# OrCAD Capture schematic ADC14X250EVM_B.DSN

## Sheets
1 PAGE1 BLOCK DIAGRAM: title: BLOCK DIAGRAM; rev: B; note: ADC14X250 EVM
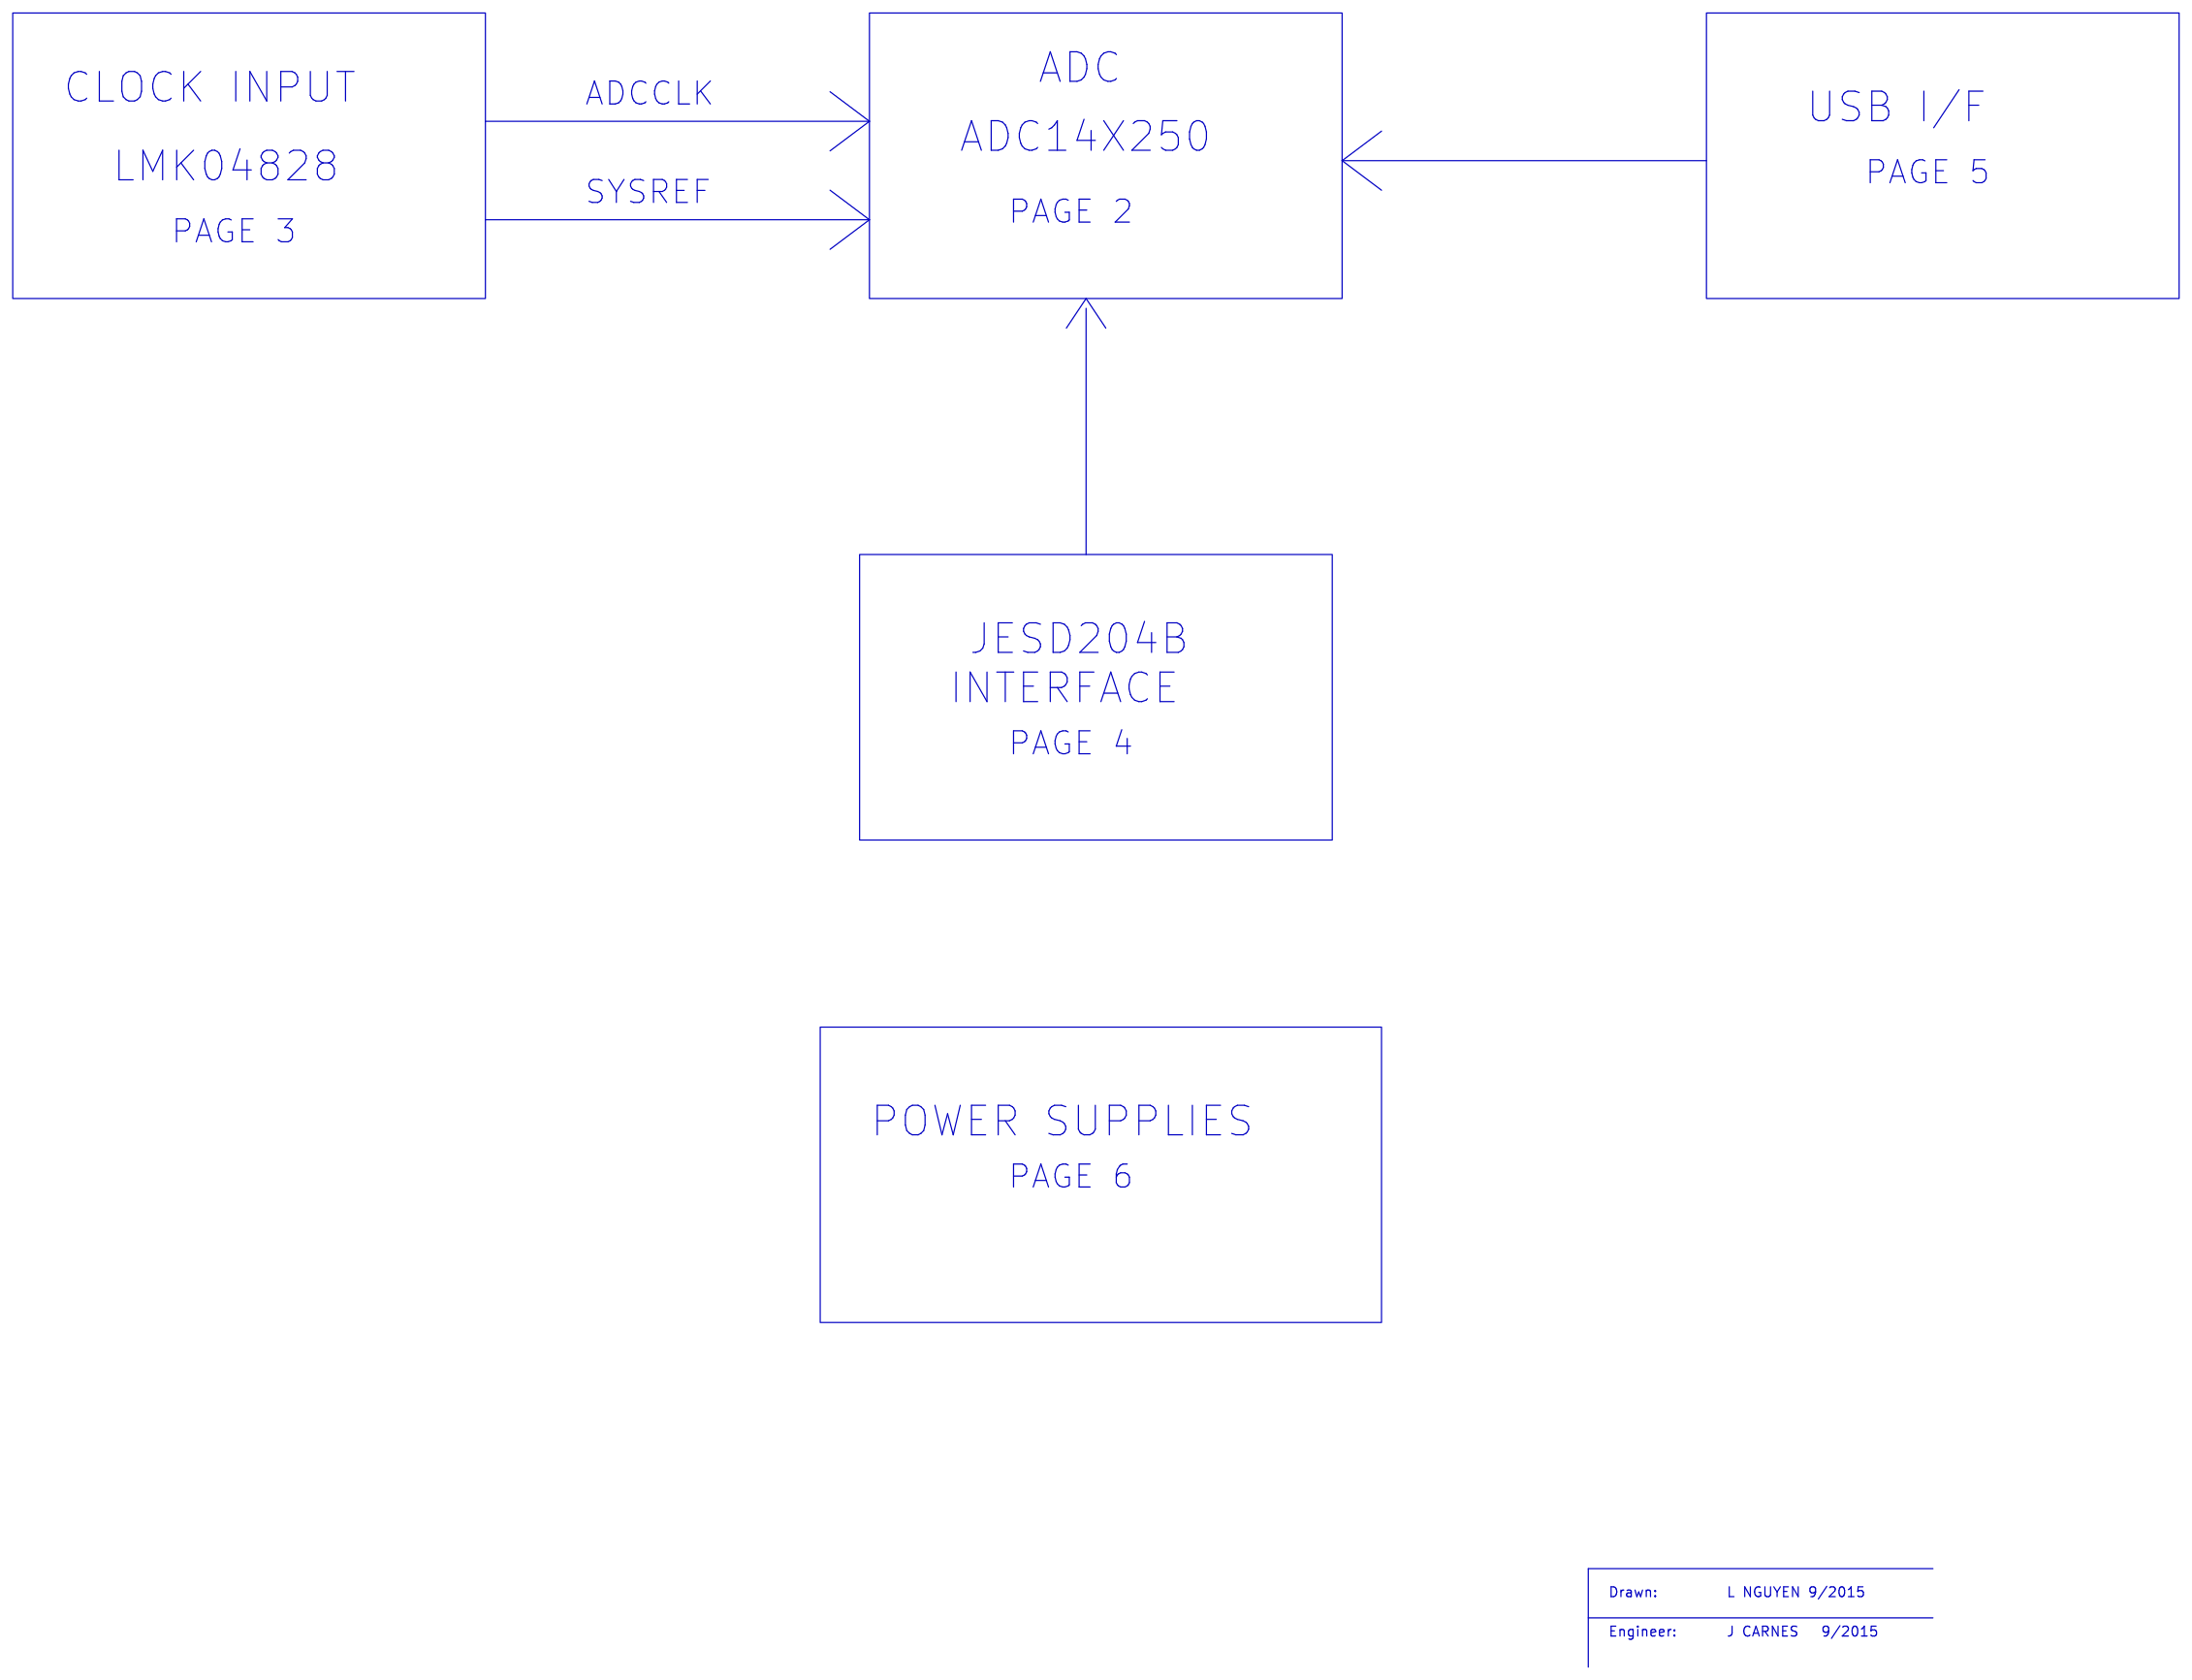
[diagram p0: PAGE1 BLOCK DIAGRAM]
2 PAGE2 ADC: size B; title: ADC14X250
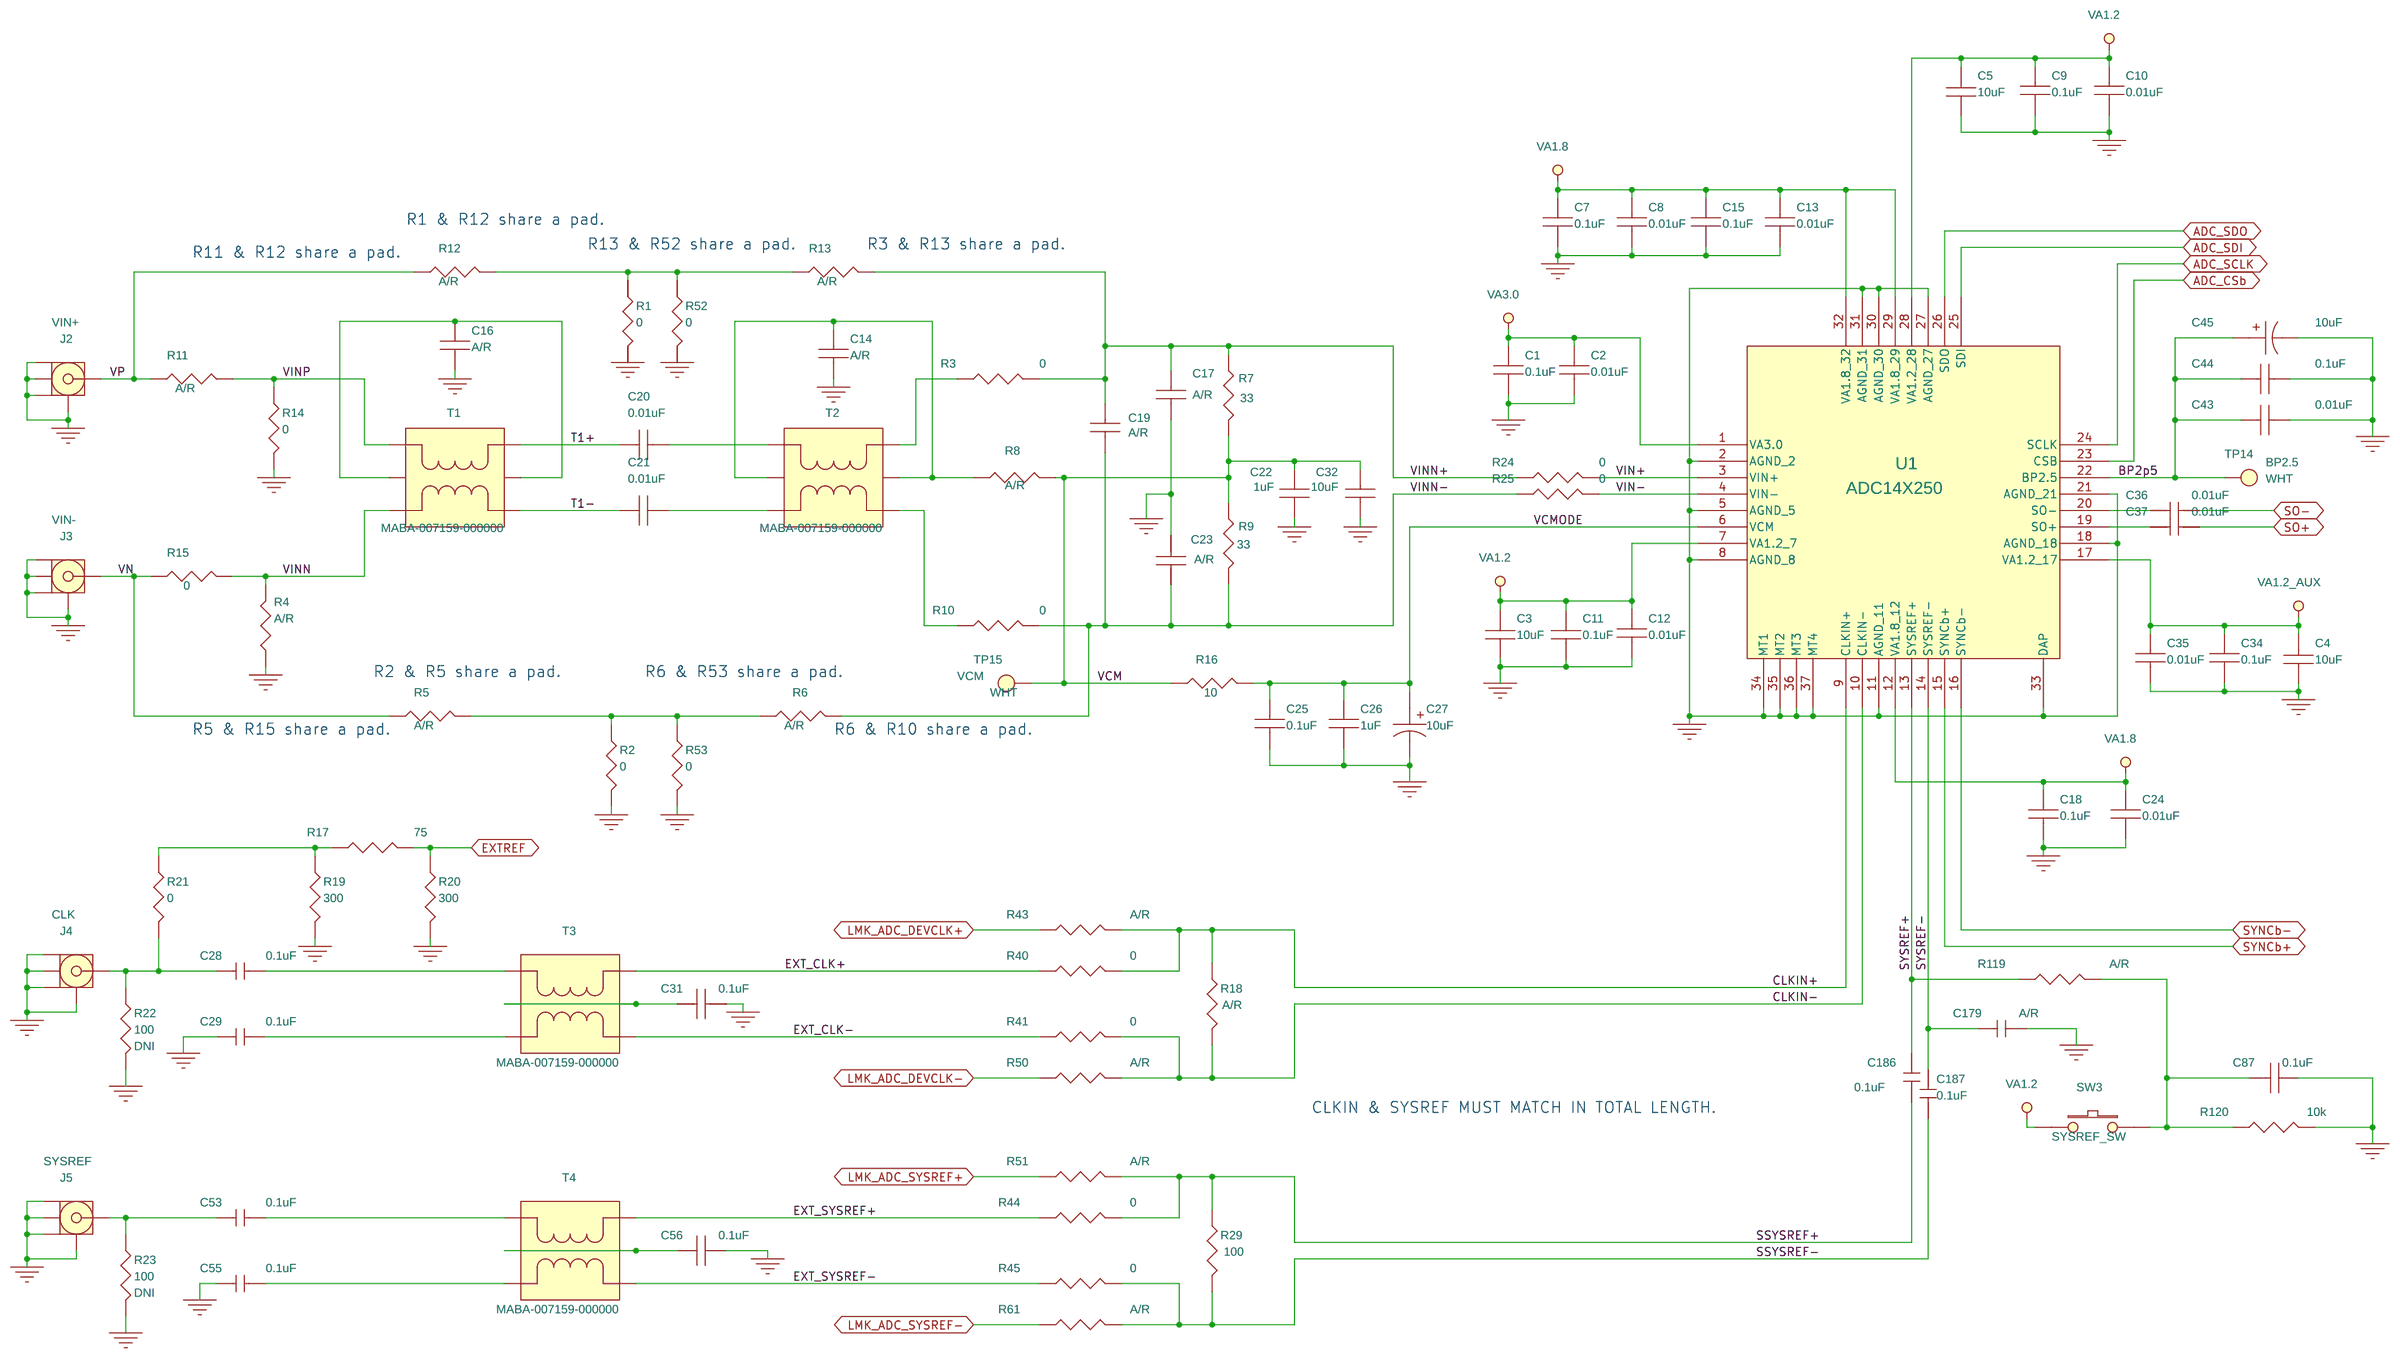
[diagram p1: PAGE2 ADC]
3 PAGE3 LMK: size B; title: LMK04828
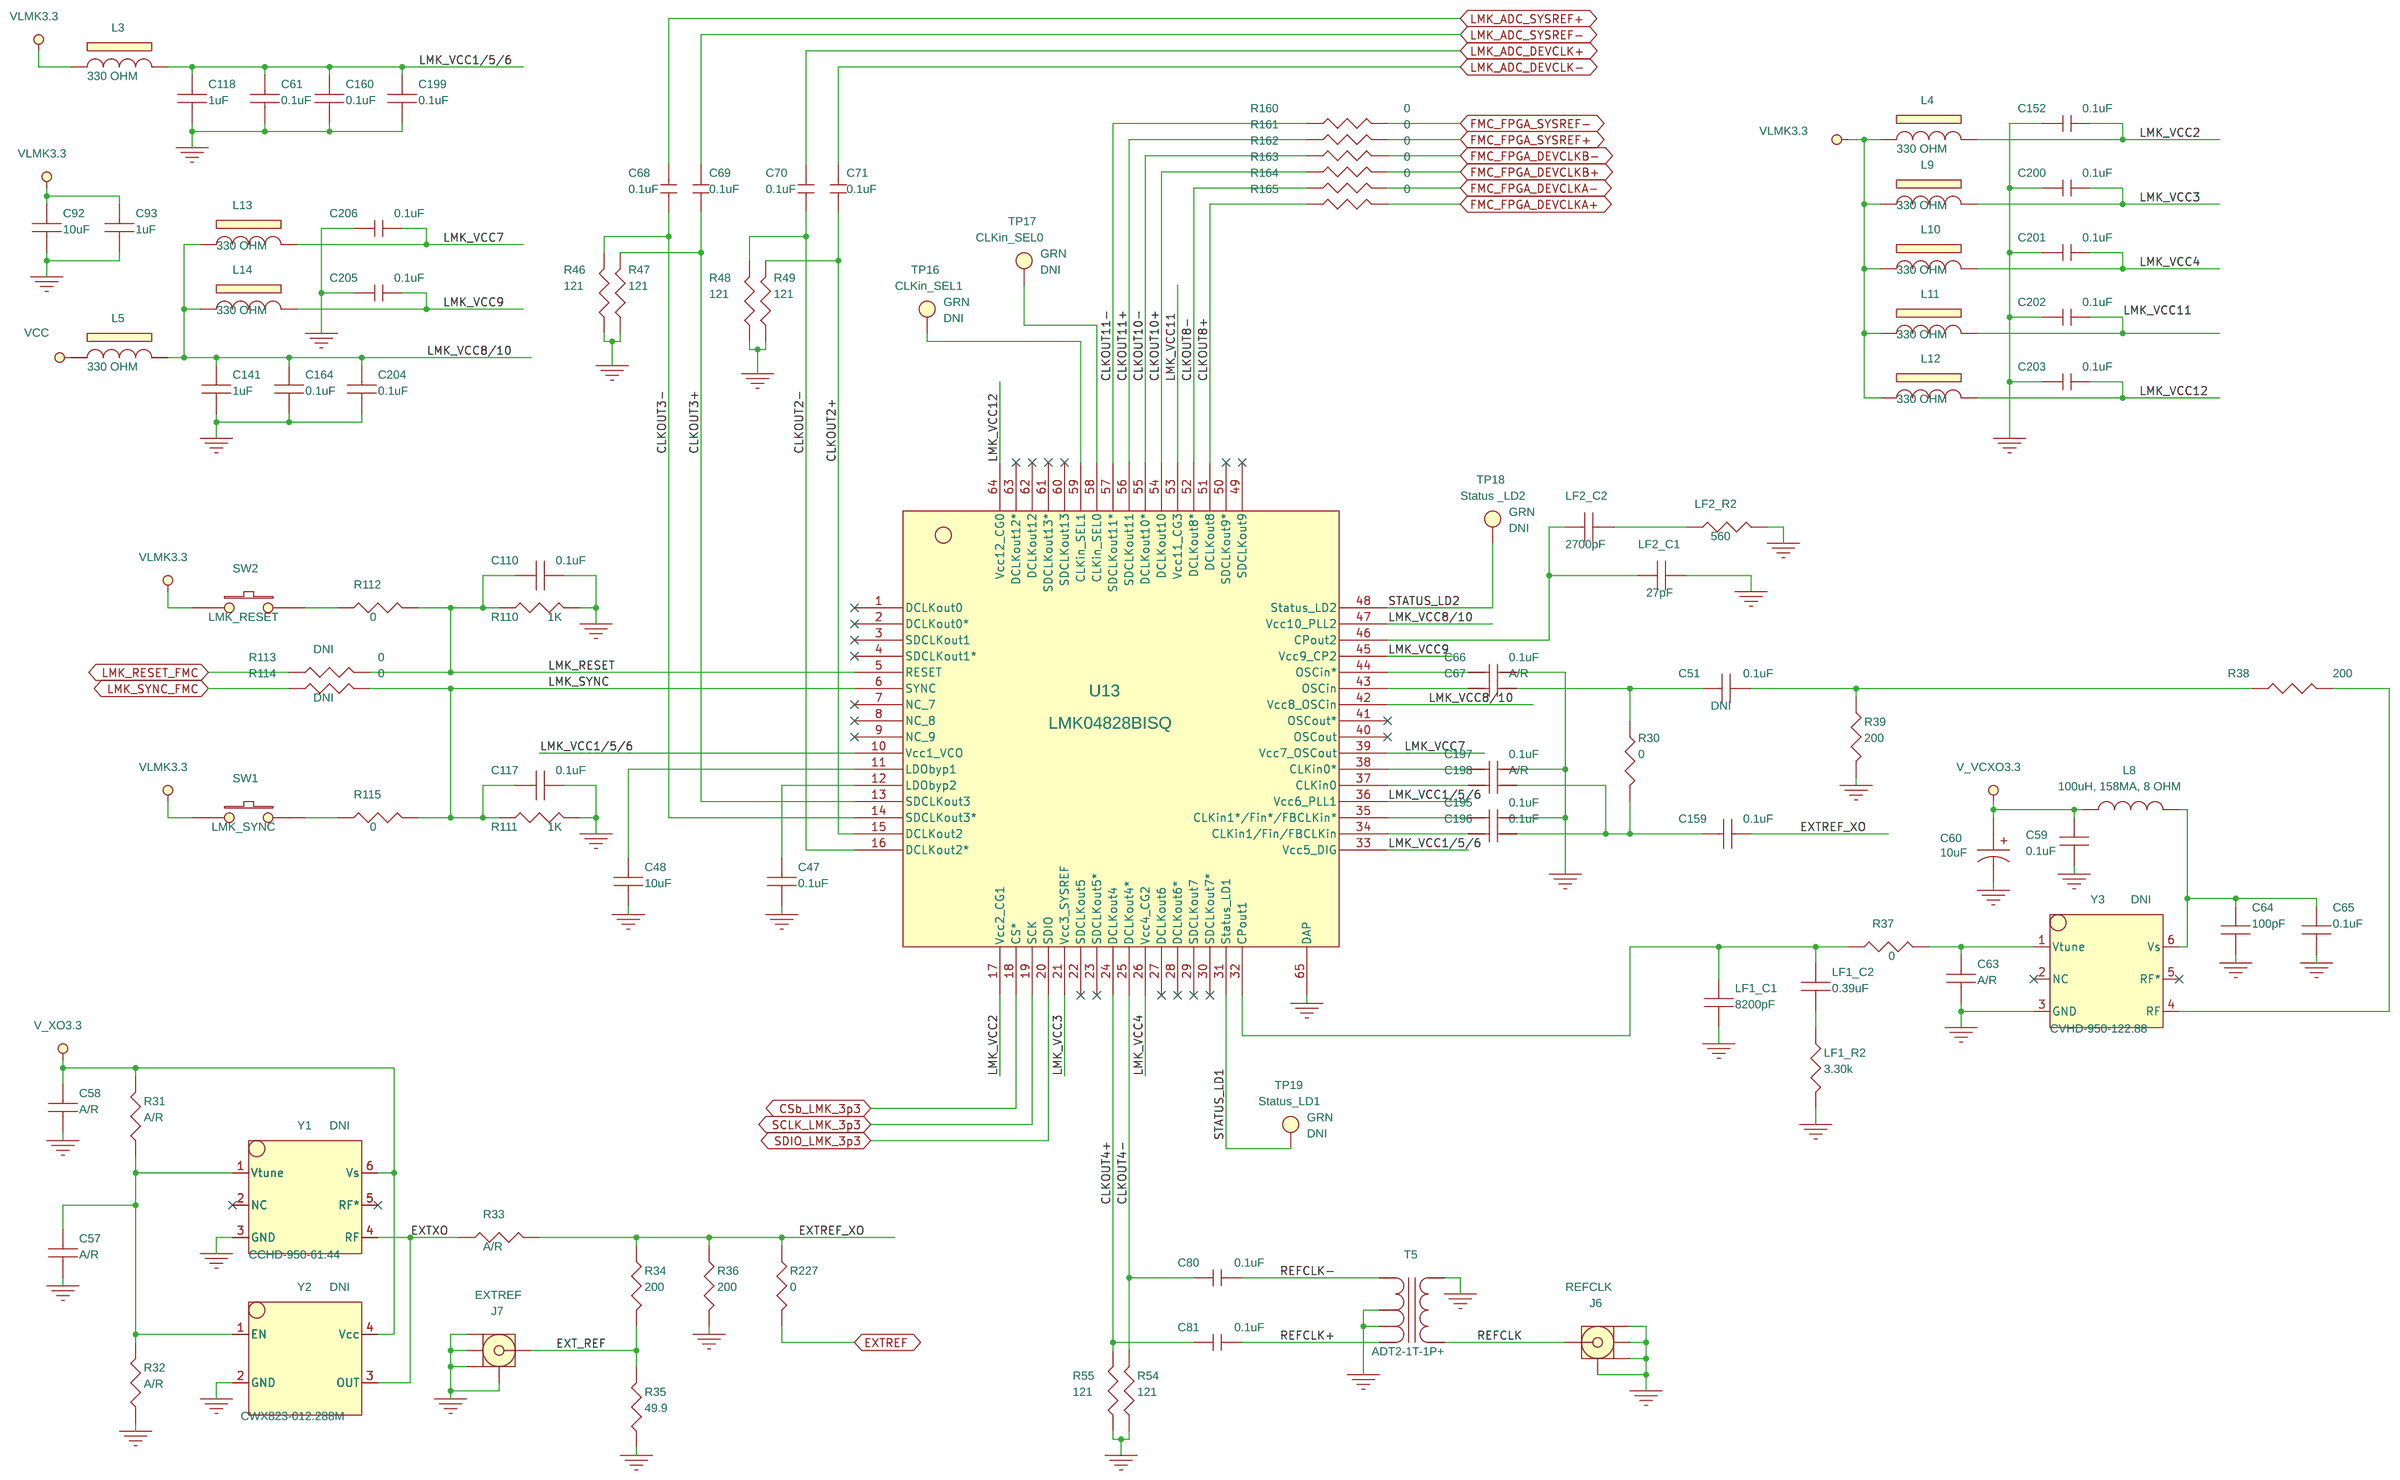
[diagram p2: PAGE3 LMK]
4 PAGE4 FMC: size B; title: FMC
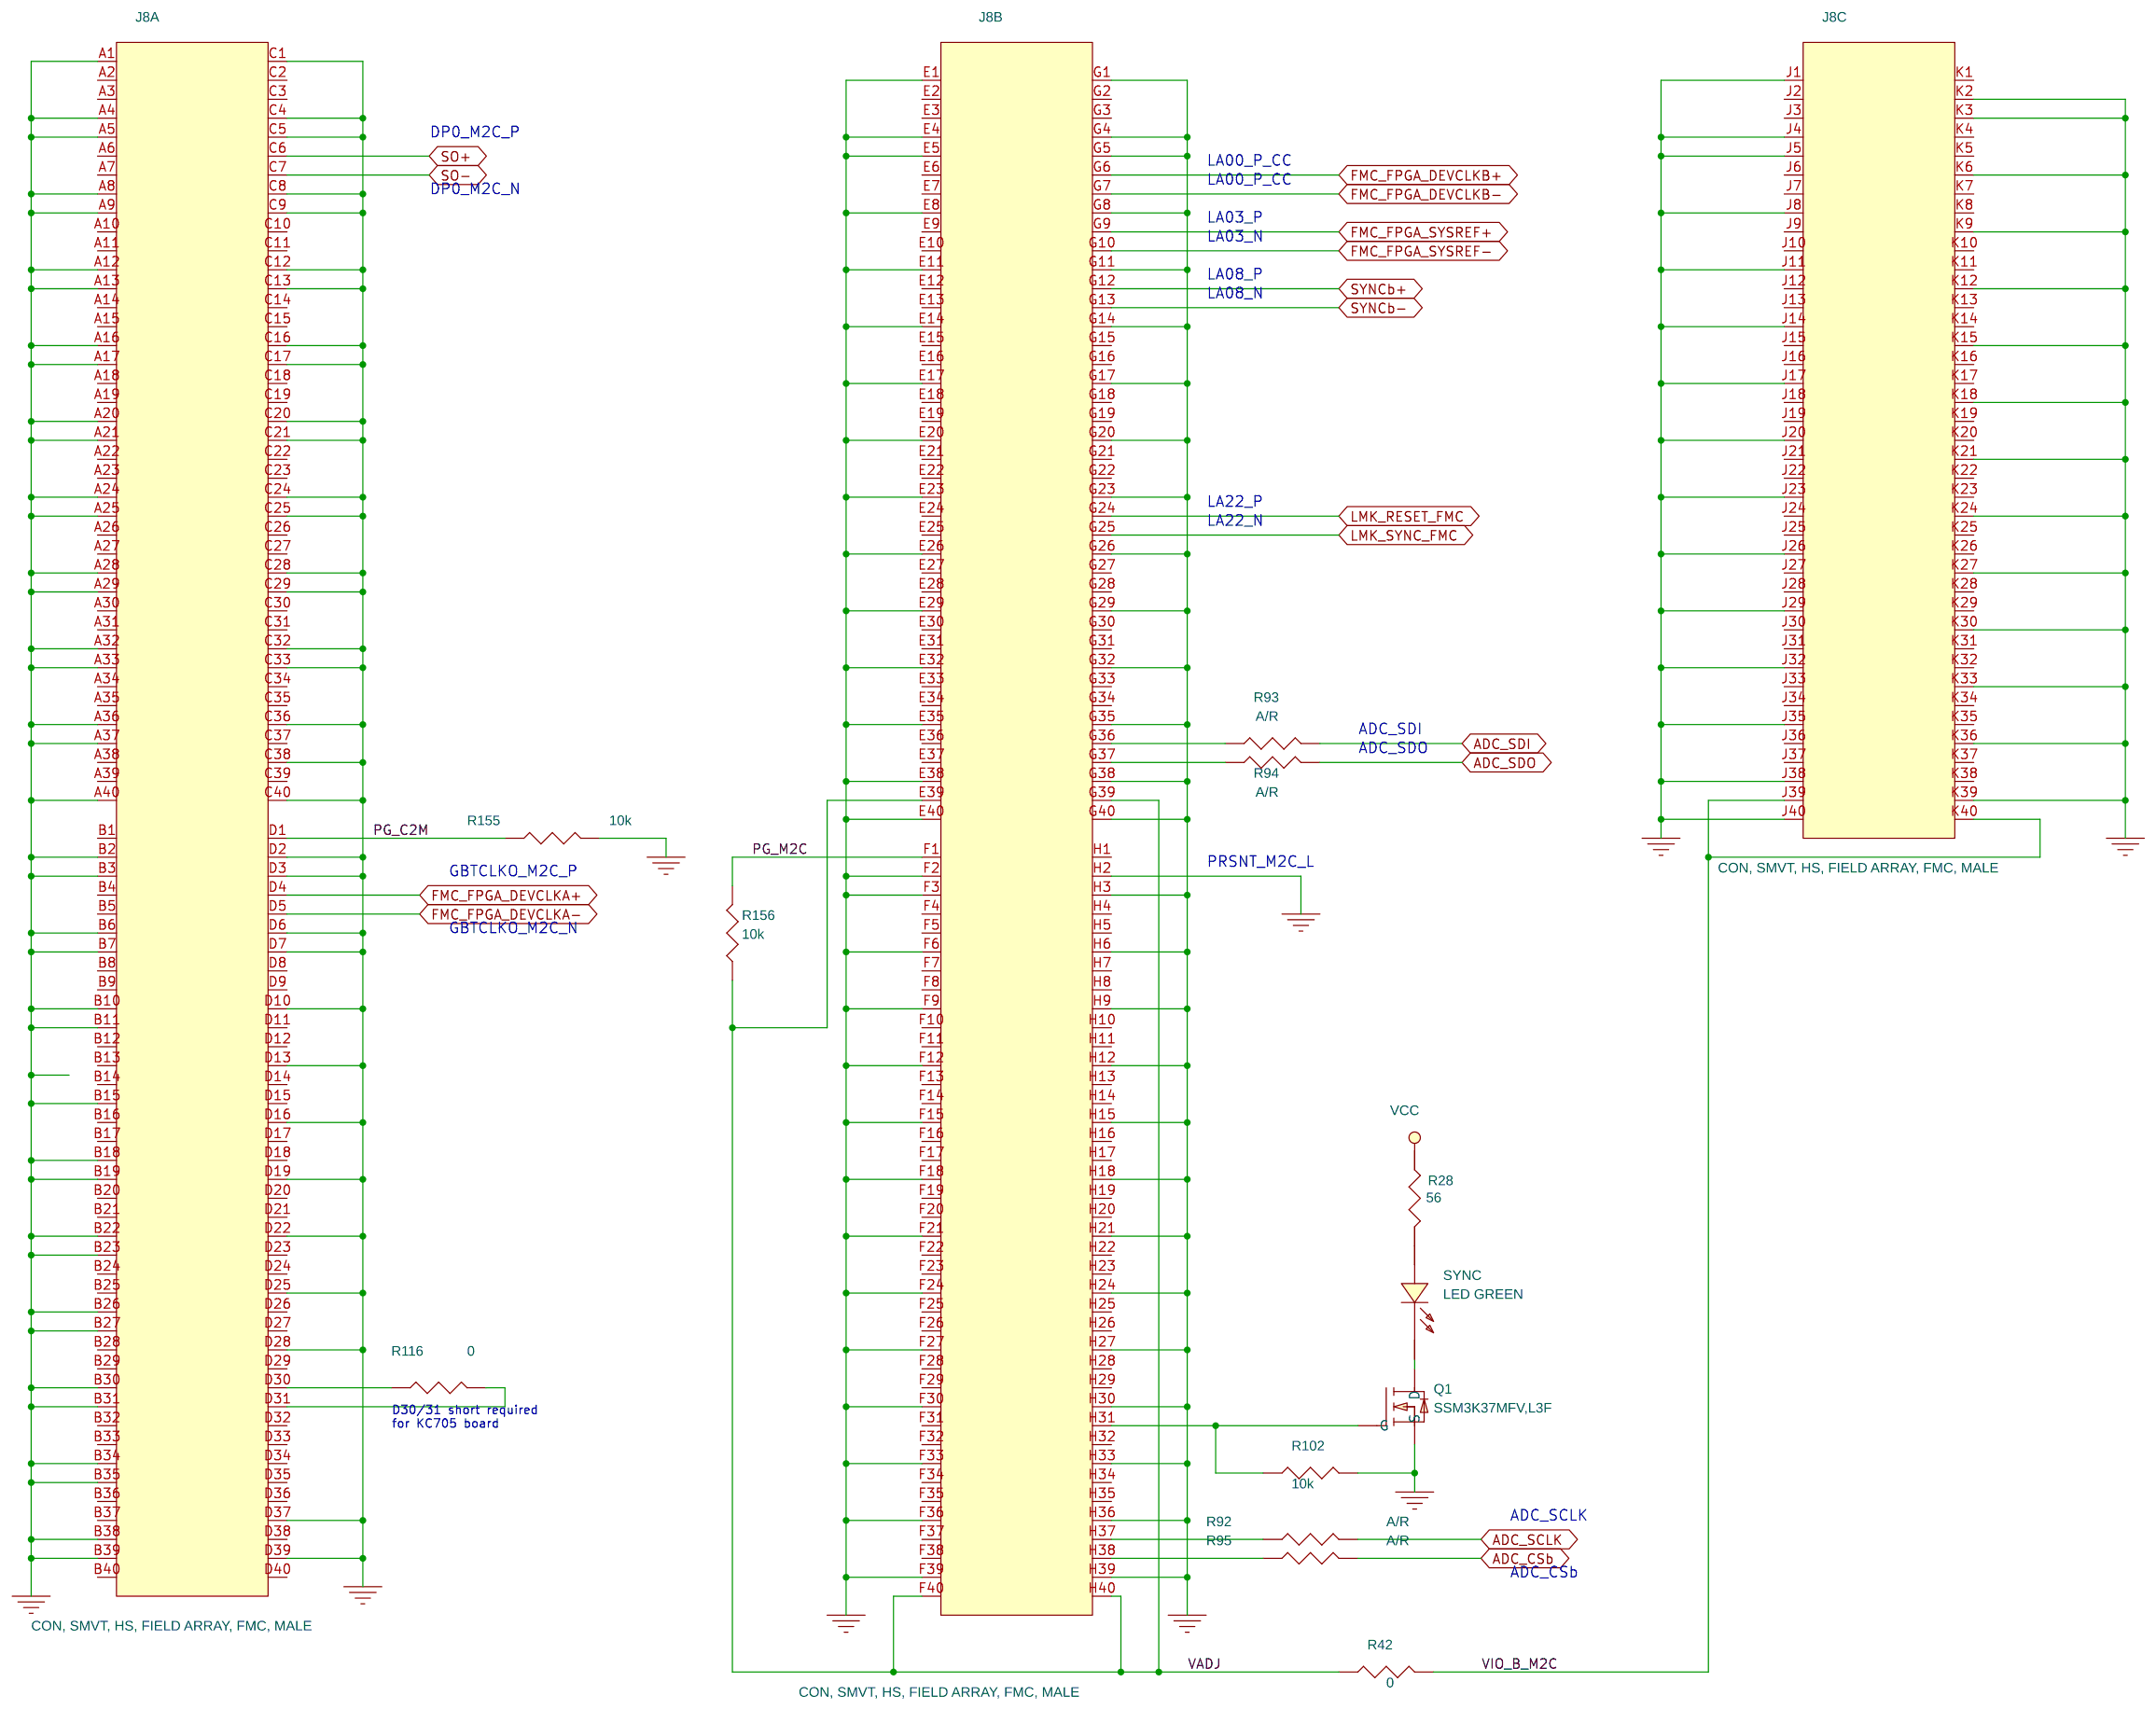
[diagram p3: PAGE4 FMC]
5 PAGE5 INTERFACE: size B; title: USB I/F
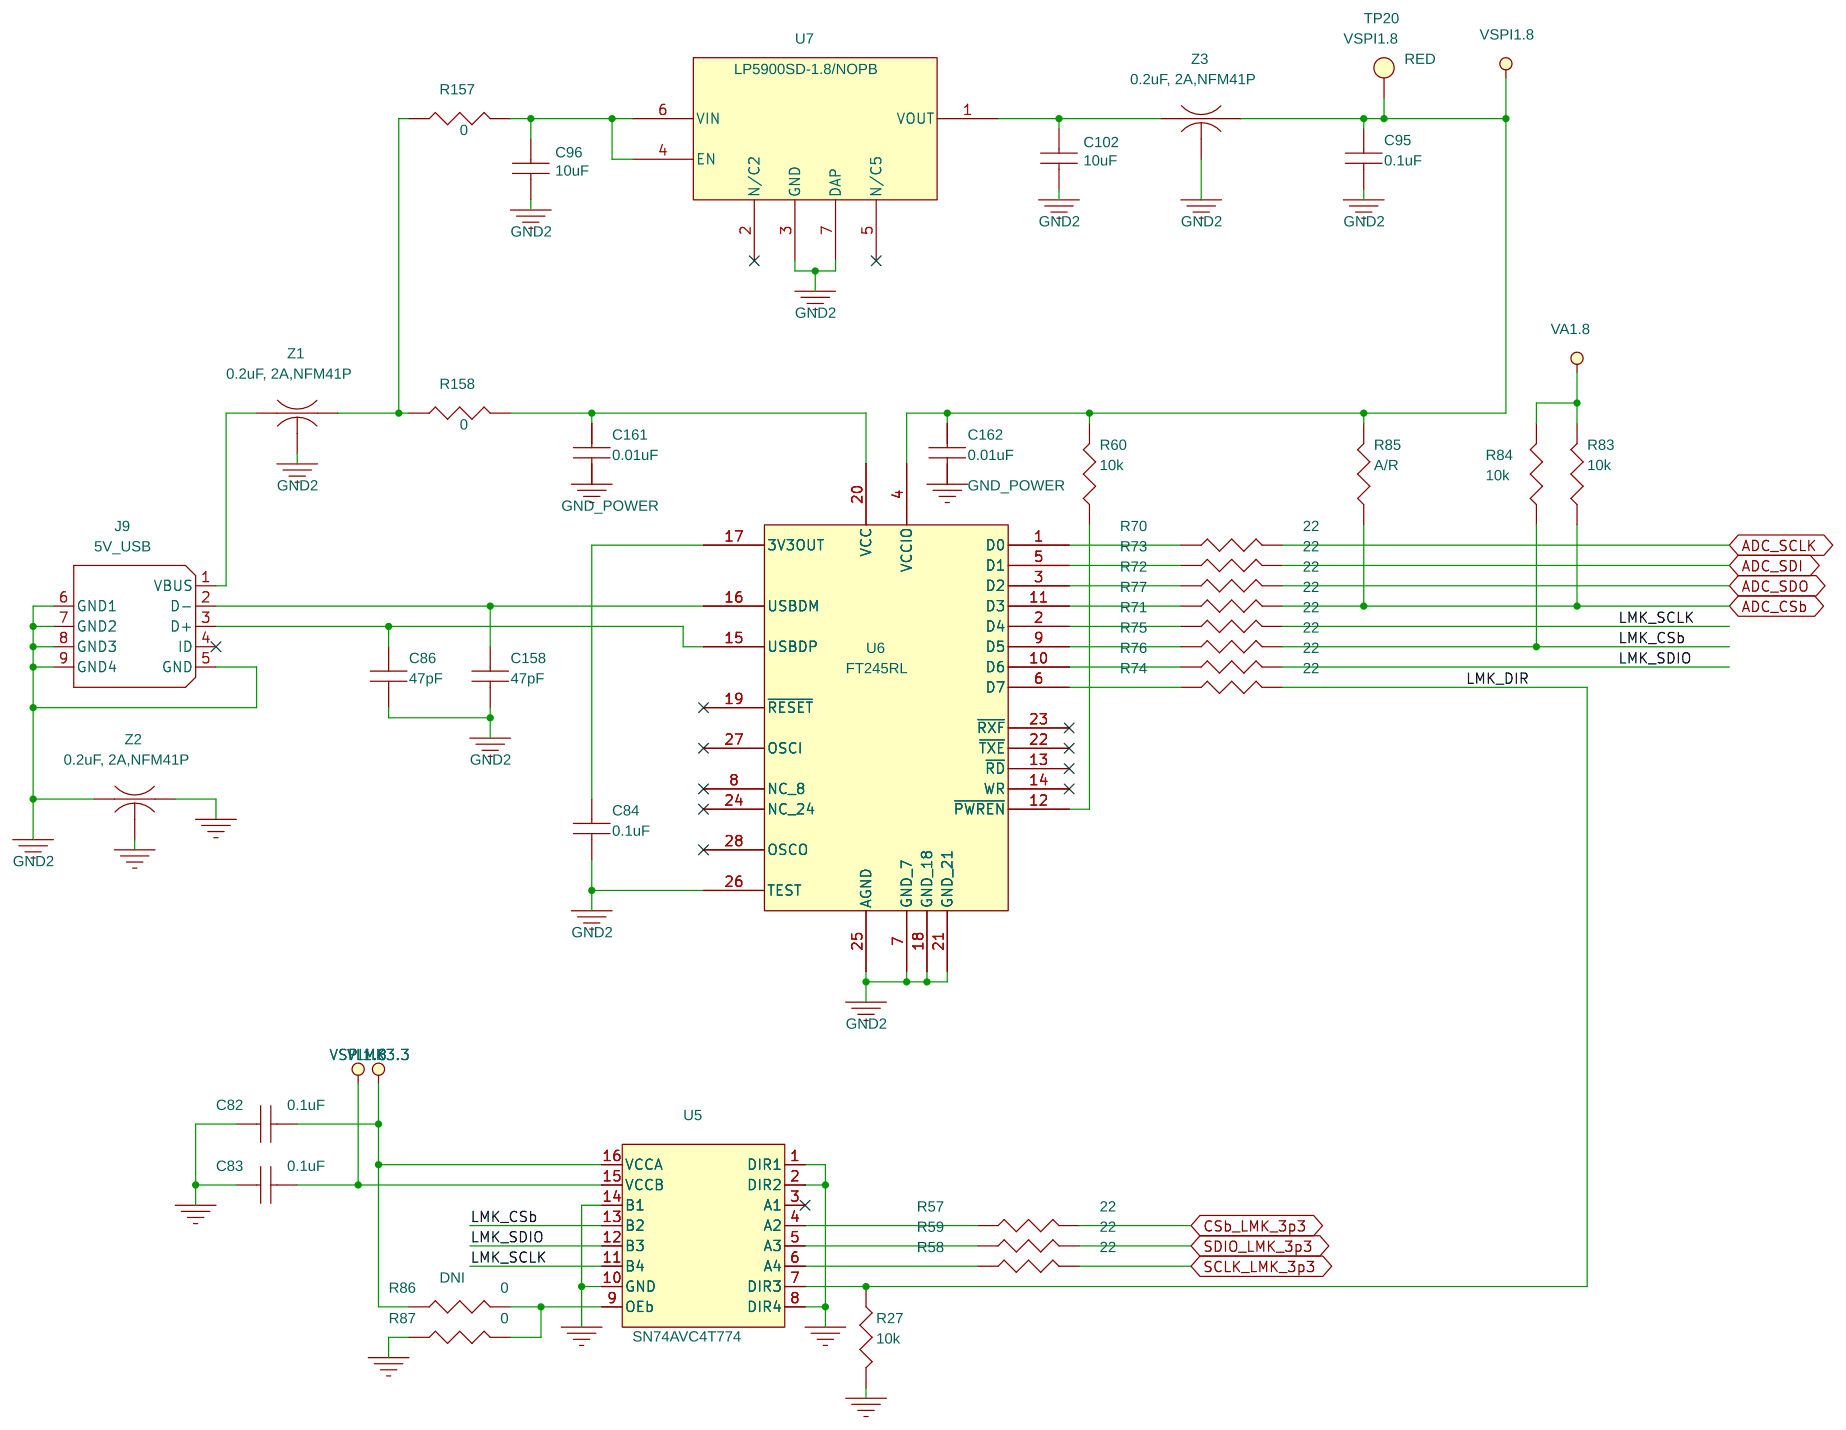
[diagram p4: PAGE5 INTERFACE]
6 PAGE6 POWER: size B; title: POWER
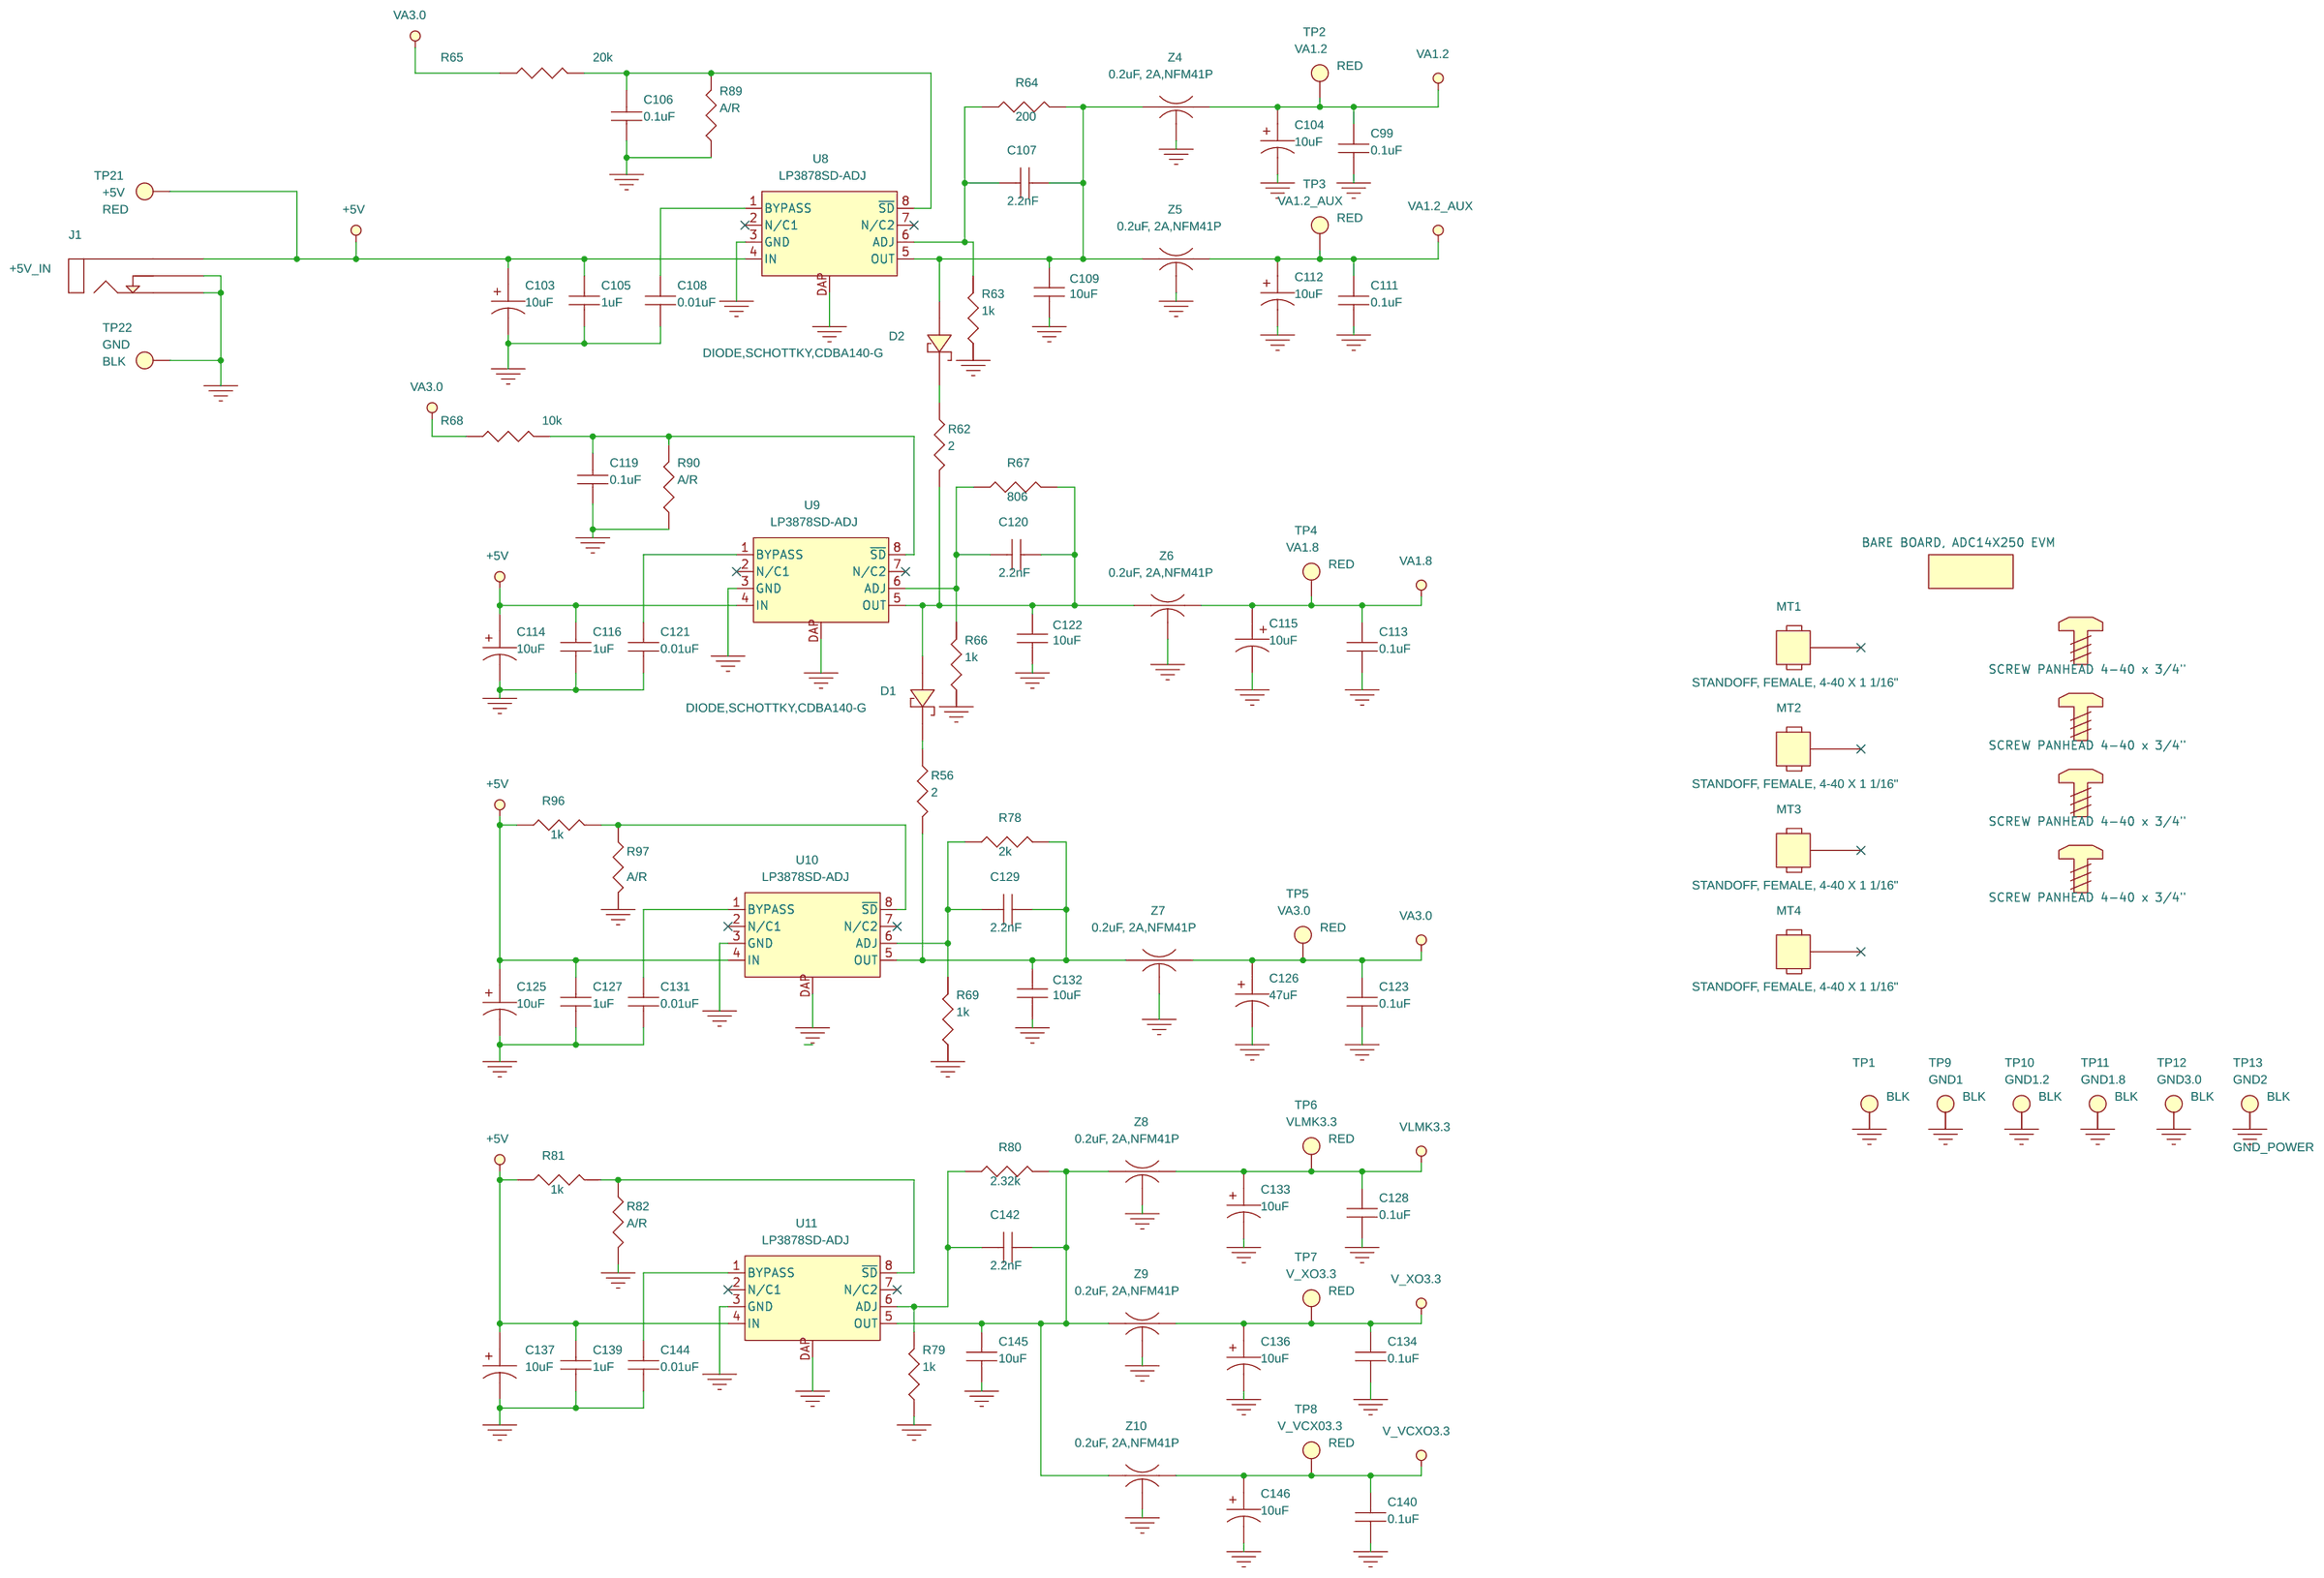
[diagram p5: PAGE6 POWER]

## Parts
sheet PAGE2 ADC
C1  0.1uF  [C0402_NO_SS]
C2  0.01uF  [0201]
C3  10uF  [C0402_NO_SS]
C4  10uF  [C0402_NO_SS]
C5  10uF  [C0402_NO_SS]
C7  0.1uF  [C0402_NO_SS]
C8  0.01uF  [0201]
C9  0.1uF  [C0402_NO_SS]
C10  0.01uF  [0201]
C11  0.1uF  [C0402_NO_SS]
C12  0.01uF  [0201]
C13  0.01uF  [0201]
C14  A/R  [C0402_NO_SS]
C15  0.1uF  [C0402_NO_SS]
C16  A/R  [C0402_NO_SS]
C17  A/R  [0201]
C18  0.1uF  [C0402_NO_SS]
C19  A/R  [C0402_NO_SS]
C20  0.01uF  [C0402_NO_SS]
C21  0.01uF  [C0402_NO_SS]
C22  1uF  [C0402_NO_SS]
C23  A/R  [0201]
C24  0.01uF  [0201]
C25  0.1uF  [0201]
C26  1uF  [0508]
C27  10uF  [cap_a-case]
C28  0.1uF  [0603]
C29  0.1uF  [0603]
C31  0.1uF  [0603]
C32  10uF  [0612]
C34  0.1uF  [C0402_NO_SS]
C35  0.01uF  [0201]
C36  0.01uF  [0201]
C37  0.01uF  [0201]
C43  0.01uF  [0201]
C44  0.1uF  [C0402_NO_SS]
C45  10uF  [cap_a-case]
C53  0.1uF  [0603]
C55  0.1uF  [0603]
C56  0.1uF  [0603]
C87  0.1uF  [smd_size0402]
C179  A/R  [0201]
C186  0.1uF  [0201]
C187  0.1uF  [0201]
J2  CONN, SMA, JACK, 50 OHM, EDGE  [con_sma-edge]
J3  CONN, SMA, JACK, 50 OHM, EDGE  [con_sma-edge]
J4  CONN, SMA, JACK, 50 OHM, EDGE  [con_sma-edge]
J5  CONN, SMA, JACK, 50 OHM, EDGE  [con_sma-edge]
R1  0  [C0402_NO_SS]
R2  0  [C0402_NO_SS]
R3  0  [0201]
R4  A/R  [C0402_NO_SS]
R5  A/R  [C0402_NO_SS]
R6  A/R  [C0402_NO_SS]
R7  33  [C0402_NO_SS]
R8  A/R  [C0402_NO_SS]
R9  33  [C0402_NO_SS]
R10  0  [0201]
R11  A/R  [C0402_NO_SS]
R12  A/R  [C0402_NO_SS]
R13  A/R  [C0402_NO_SS]
R14  0  [C0402_NO_SS]
R15  0  [C0402_NO_SS]
R16  10  [C0402_NO_SS]
R17  75  [0402]
R18  A/R  [0201]
R19  300  [0402]
R20  300  [0402]
R21  0  [C0402_NO_SS]
R22  100  [C0402_NO_SS]
R23  100  [C0402_NO_SS]
R24  0  [0201]
R25  0  [0201]
R29  100  [0201]
R40  0  [C0402_NO_SS]
R41  0  [C0402_NO_SS]
R43  A/R  [C0402_NO_SS]
R44  0  [C0402_NO_SS]
R45  0  [C0402_NO_SS]
R50  A/R  [C0402_NO_SS]
R51  A/R  [C0402_NO_SS]
R52  0  [C0402_NO_SS]
R53  0  [C0402_NO_SS]
R61  A/R  [C0402_NO_SS]
R119  A/R  [0201]
R120  10k  [C0402_NO_SS]
SW3  SW, PUSHBUTTON, SPST-NO  [SW_RESET_PTS635]
T1  MABA-007159-000000  [MABA-007159-000000]
T2  MABA-007159-000000  [MABA-007159-000000]
T3  MABA-007159-000000  [MABA-007159-000000]
T4  MABA-007159-000000  [MABA-007159-000000]
TP14  WHT  [TP_THVT_100_RND]
TP15  WHT  [TP_THVT_100_RND]
U1  ADC14X250  [QFN_32_IRONWOOD_0p5mm]
sheet PAGE3 LMK
C47  0.1uF  [C0402_NO_SS]
C48  10uF  [0805]
C51  0.1uF  [C0402_NO_SS]
C57  A/R  [C0402_NO_SS]
C58  A/R  [C0402_NO_SS]
C59  0.1uF  [0603]
C60  10uF  [smd_size3216]
C61  0.1uF  [C0402_NO_SS]
C63  A/R  [C0402_NO_SS]
C64  100pF  [0603]
C65  0.1uF  [0603]
C66  0.1uF  [0201]
C67  A/R  [0201]
C68  0.1uF  [0201]
C69  0.1uF  [0201]
C70  0.1uF  [0201]
C71  0.1uF  [0201]
C80  0.1uF  [0201]
C81  0.1uF  [0201]
C92  10uF  [0805]
C93  1uF  [C0402_NO_SS]
C110  0.1uF  [smd_size0402]
C117  0.1uF  [smd_size0402]
C118  1uF  [C0402_NO_SS]
C141  1uF  [C0402_NO_SS]
C152  0.1uF  [0201]
C159  0.1uF  [C0402_NO_SS]
C160  0.1uF  [C0402_NO_SS]
C164  0.1uF  [C0402_NO_SS]
C195  0.1uF  [0201]
C196  0.1uF  [0201]
C197  0.1uF  [0201]
C198  A/R  [0201]
C199  0.1uF  [C0402_NO_SS]
C200  0.1uF  [0201]
C201  0.1uF  [0201]
C202  0.1uF  [0201]
C203  0.1uF  [0201]
C204  0.1uF  [C0402_NO_SS]
C205  0.1uF  [0201]
C206  0.1uF  [0201]
J6  CONN, SMA, JACK, 50 OHM, EDGE  [con_sma-edge]
J7  CONN, SMA, JACK, 50 OHM, EDGE  [con_sma-edge]
L3  330 OHM  [r0603]
L4  330 OHM  [r0603]
L5  330 OHM  [r0603]
L8  100uH, 158MA, 8 OHM  [smd_size1812r]
L9  330 OHM  [r0603]
L10  330 OHM  [r0603]
L11  330 OHM  [r0603]
L12  330 OHM  [r0603]
L13  330 OHM  [r0603]
L14  330 OHM  [r0603]
LF1_C1  8200pF  [0603]
LF1_C2  0.39uF  [0603]
LF1_R2  3.30k  [0603]
LF2_C1  27pF  [0603]
LF2_C2  2700pF  [0603]
LF2_R2  560  [0603]
R30  0  [0201]
R31  A/R  [C0402_NO_SS]
R32  A/R  [C0402_NO_SS]
R33  A/R  [C0402_NO_SS]
R34  200  [C0402_NO_SS]
R35  49.9  [C0402_NO_SS]
R36  200  [C0402_NO_SS]
R37  0  [0603]
R38  200  [C0402_NO_SS]
R39  200  [C0402_NO_SS]
R46  121  [C0402_NO_SS]
R47  121  [C0402_NO_SS]
R48  121  [C0402_NO_SS]
R49  121  [C0402_NO_SS]
R54  121  [C0402_NO_SS]
R55  121  [C0402_NO_SS]
R110  1K  [smd_size0402]
R111  1K  [smd_size0402]
R112  0  [C0402_NO_SS]
R113  0  [C0402_NO_SS]
R114  0  [C0402_NO_SS]
R115  0  [C0402_NO_SS]
R160  0  [C0402_NO_SS]
R161  0  [C0402_NO_SS]
R162  0  [C0402_NO_SS]
R163  0  [C0402_NO_SS]
R164  0  [C0402_NO_SS]
R165  0  [C0402_NO_SS]
R227  0  [C0402_NO_SS]
SW1  SW, PUSHBUTTON, SPST-NO  [SW_RESET_PTS635]
SW2  SW, PUSHBUTTON, SPST-NO  [SW_RESET_PTS635]
T5  ADT2-1T-1P+  [ADT1-1WT]
TP16  GRN  [TP_THVT_100_RND]
TP17  GRN  [TP_THVT_100_RND]
TP18  GRN  [TP_THVT_100_RND]
TP19  GRN  [TP_THVT_100_RND]
U13  LMK04828BISQ  [WQFN_64_360x360_0p5mm_PWRPAD]
Y1  CCHD-950-61.44  [soic6_100_wg272_l560]
Y2  CWX823-012.288M  [CWX813]
Y3  CVHD-950-122.88  [soic6_100_wg272_l560]
sheet PAGE4 FMC
J8  CON, SMVT, HS, FIELD ARRAY, FMC, MALE  [CON_SMVT_40x10_SEAM_MTG]  (sections A,B,C)
Q1  SSM3K37MFV,L3F  [sot-723]
R28  56  [smd_size0402]
R42  0  [0603]
R92  A/R  [C0402_NO_SS]
R93  A/R  [C0402_NO_SS]
R94  A/R  [C0402_NO_SS]
R95  A/R  [C0402_NO_SS]
R102  10k  [C0402_NO_SS]
R116  0  [0603]
R155  10k  [0603]
R156  10k  [0603]
SYNC  LED GREEN  [LED_0805]
sheet PAGE5 INTERFACE
C82  0.1uF  [smd_size0402]
C83  0.1uF  [smd_size0402]
C84  0.1uF  [C0402_NO_SS]
C86  47pF  [C0402_NO_SS]
C95  0.1uF  [0603]
C96  10uF  [smd_size1206]
C102  10uF  [smd_size1206]
C158  47pF  [C0402_NO_SS]
C161  0.01uF  [C0402_NO_SS]
C162  0.01uF  [C0402_NO_SS]
J9  CONN, USB, MINI AB, R/A, SMT  [CON_SMRT_USBMNE20_F]
R27  10k  [C0402_NO_SS]
R57  22  [C0402_NO_SS]
R58  22  [C0402_NO_SS]
R59  22  [C0402_NO_SS]
R60  10k  [C0402_NO_SS]
R70  22  [C0402_NO_SS]
R71  22  [C0402_NO_SS]
R72  22  [C0402_NO_SS]
R73  22  [C0402_NO_SS]
R74  22  [C0402_NO_SS]
R75  22  [C0402_NO_SS]
R76  22  [C0402_NO_SS]
R77  22  [C0402_NO_SS]
R83  10k  [C0402_NO_SS]
R84  10k  [C0402_NO_SS]
R85  A/R  [C0402_NO_SS]
R86  0  [smd_size0402]
R87  0  [smd_size0402]
R157  0  [0603]
R158  0  [0603]
TP20  RED  [TP_THVT_100_RND]
U5  SN74AVC4T774  [tssop16_pw]
U6  FT245RL  [FT245RL]
U7  LP5900SD-1.8/NOPB  [sc-mkt-sdb06a_6llp]
Z1  0.2uF, 2A,NFM41P  [nfm41p]
Z2  0.2uF, 2A,NFM41P  [nfm41p]
Z3  0.2uF, 2A,NFM41P  [nfm41p]
sheet PAGE6 POWER
C99  0.1uF  [0603]
C103  10uF  [cap_a-case]
C104  10uF  [cap_a-case]
C105  1uF  [smd_size1206]
C106  0.1uF  [C0402_NO_SS]
C107  2.2nF  [smd_size0603]
C108  0.01uF  [C0402_NO_SS]
C109  10uF  [smd_size1206]
C111  0.1uF  [0603]
C112  10uF  [cap_a-case]
C113  0.1uF  [0603]
C114  10uF  [cap_a-case]
C115  10uF  [cap_a-case]
C116  1uF  [smd_size1206]
C119  0.1uF  [C0402_NO_SS]
C120  2.2nF  [smd_size0603]
C121  0.01uF  [C0402_NO_SS]
C122  10uF  [smd_size1206]
C123  0.1uF  [0603]
C125  10uF  [cap_a-case]
C126  47uF  [cap_a-case]
C127  1uF  [smd_size1206]
C128  0.1uF  [0603]
C129  2.2nF  [smd_size0603]
C131  0.01uF  [C0402_NO_SS]
C132  10uF  [smd_size1206]
C133  10uF  [cap_a-case]
C134  0.1uF  [0603]
C136  10uF  [cap_a-case]
C137  10uF  [cap_a-case]
C139  1uF  [smd_size1206]
C140  0.1uF  [0603]
C142  2.2nF  [smd_size0603]
C144  0.01uF  [C0402_NO_SS]
C145  10uF  [smd_size1206]
C146  10uF  [cap_a-case]
D1  DIODE,SCHOTTKY,CDBA140-G  [ZENER_DO_214AC]
D2  DIODE,SCHOTTKY,CDBA140-G  [ZENER_DO_214AC]
J1  CONN, JACK, PWR  [CON_RAPC722_JACK_THVT_3]
MT1  STANDOFF, FEMALE, 4-40 X 1 1/16"  [MFG125_PLATED]
MT2  STANDOFF, FEMALE, 4-40 X 1 1/16"  [MFG125_PLATED]
MT3  STANDOFF, FEMALE, 4-40 X 1 1/16"  [MFG125_PLATED]
MT4  STANDOFF, FEMALE, 4-40 X 1 1/16"  [MFG125_PLATED]
R56  2  [0603]
R62  2  [0603]
R63  1k  [smd_size0402]
R64  200  [smd_size0402]
R65  20k  [C0402_NO_SS]
R66  1k  [smd_size0402]
R67  806  [smd_size0402]
R68  10k  [smd_size0402]
R69  1k  [smd_size0402]
R78  2k  [smd_size0402]
R79  1k  [smd_size0402]
R80  2.32k  [smd_size0402]
R81  1k  [smd_size0402]
R82  A/R  [smd_size0402]
R89  A/R  [smd_size0402]
R90  A/R  [smd_size0402]
R96  1k  [smd_size0402]
R97  A/R  [smd_size0402]
TP1  BLK  [TP_THVT_100_RND_GND]
TP2  RED  [TP_THVT_100_RND]
TP3  RED  [TP_THVT_100_RND]
TP4  RED  [TP_THVT_100_RND]
TP5  RED  [TP_THVT_100_RND]
TP6  RED  [TP_THVT_100_RND]
TP7  RED  [TP_THVT_100_RND]
TP8  RED  [TP_THVT_100_RND]
TP9  BLK  [TP_THVT_100_RND_GND]
TP10  BLK  [TP_THVT_100_RND_GND]
TP11  BLK  [TP_THVT_100_RND_GND]
TP12  BLK  [TP_THVT_100_RND_GND]
TP13  BLK  [TP_THVT_100_RND_GND]
TP21  RED  [testpoint_62dia]
TP22  BLK  [testpoint_62dia]
U8  LP3878SD-ADJ  [sc-mkt-sdc08a_llp]
U9  LP3878SD-ADJ  [sc-mkt-sdc08a_llp]
U10  LP3878SD-ADJ  [sc-mkt-sdc08a_llp]
U11  LP3878SD-ADJ  [sc-mkt-sdc08a_llp]
Z4  0.2uF, 2A,NFM41P  [nfm41p]
Z5  0.2uF, 2A,NFM41P  [nfm41p]
Z6  0.2uF, 2A,NFM41P  [nfm41p]
Z7  0.2uF, 2A,NFM41P  [nfm41p]
Z8  0.2uF, 2A,NFM41P  [nfm41p]
Z9  0.2uF, 2A,NFM41P  [nfm41p]
Z10  0.2uF, 2A,NFM41P  [nfm41p]
Z_BOARD1  BARE BOARD, ADC14X250 EVM
Z_SCREW1  SCREW PANHEAD 4-40 x 3/4"
Z_SCREW2  SCREW PANHEAD 4-40 x 3/4"
Z_SCREW3  SCREW PANHEAD 4-40 x 3/4"
Z_SCREW4  SCREW PANHEAD 4-40 x 3/4"

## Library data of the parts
C1 C11 = Cap_0: Manufactured by: Murata Electronics North America; Mfr_Name: MURATA; Mfr_Part_Number: GRM155R61C104KA88D; Part Description: CAP CER .1UF 16V X5R 0402; Part Number: GRM155R61C104KA88D
C2 C8 C10 C12 C13 C24 C35 C43 = Cap_0: Mfr_Name: MURATA; Mfr_Part_Number: GRM033R60J103KA01D; Part Description: CAP CER 10000PF 6.3V X5R 0201; Part Number: GRM033R60J103KA01D
C3 = CAPACITOR_NON-POL: Manufactured by: Taiyo Yuden; Mfr_Name: TAIYO YUDEN; Mfr_Part_Number: AMK105CBJ106MV-F; Part Description: CAP CER 10UF 4V 20% X5R 0402; Part Number: AMK105CBJ106MV-F
C4 C5 = CAPACITOR_NON-POL: Mfr_Name: TAIYO YUDEN; Mfr_Part_Number: AMK105CBJ106MV-F; Part Description: CAP CER 10UF 4V 20% X5R 0402; Part Number: AMK105CBJ106MV-F
C7 C9 C15 C18 C34 C44 C47 C61 C84 C106 C119 C159 C160 C164 C199 C204 = Cap_0: Mfr_Name: MURATA; Mfr_Part_Number: GRM155R61C104KA88D; Part Description: CAP CER .1UF 16V X5R 0402; Part Number: GRM155R61C104KA88D
C14 C57 C63 = Cap_0: Mfr_Name: N/A; Note: DNI
C16 C17 C19 C23 C58 = Capacitor_0: Mfr_Name: N/A; Note: DNI
C20 C21 C108 C121 C131 C144 C161 C162 = Cap_0: Mfr_Name: MURATA; Mfr_Part_Number: GRM155R71C103KA01D; Part Description: CAP CER 10000PF 16V 10% X7R 0402; Part Number: GRM155R71C103KA01D
C22 C93 C118 C141 = CAPACITOR_NON-POL: Mfr_Name: TDK CORP; Mfr_Part_Number: C1005X5R1A105K050BB; Part Description: CAP CER 1UF 10V 10% X5R 0402
C25 = Capacitor_0: Mfr_Name: MURATA; Mfr_Part_Number: GRM033R60J104KE19D; Part Description: CAP CER .1UF 6.3V X5R 0201; Part Number: GRM033R60J104KE19D
C26 = Capacitor_0: Mfr_Name: TDK CORP; Mfr_Part_Number: C1220X5R1A105M085AC; Part Description: CAP CER 1.0UF 10V 20% X5R 0508
C27 C60 = Cap_Polar_0: Mfr_Name: AVX CORP; Mfr_Part_Number: TAJA106M016RNJ; Part Description: CAP TANT 10UF 16V 20% 1206; Part Number: TAJA106M016RNJ
C28 C29 C53 C55 = CAP_0603_0.1uF_H
C31 C56 C59 C65 C95 C99 C111 C113 C123 C128 C134 C140 = Capacitor_0: Mfr_Name: AVX CORP; Mfr_Part_Number: 0603YC104KAT2A; Part Description: CAP CERM .1UF 10% 16V X7R 0603; Part Number: 0603YC104KAT2A
C32 = CAPACITOR_NON-POL: Manufactured by: TDK Corporation; Mfr_Name: TDK CORP; Mfr_Part_Number: C1632X5R0J106M130AC; Part Description: CAP CER 10UF 6.3V 20% X5R 1206
C36 C37 = CAP_0201_0.1uF: Mfr_Name: MURATA; Mfr_Part_Number: GRM033R71A103KA01D
C45 C103 C104 C112 C114 C115 C125 C133 C136 C137 C146 = Cap_Polar_0: Mfr_Name: AVX CORP; Mfr_Part_Number: TAJA106M016RNJ; Part Description: CAP TANTALUM 10UF 16V 20% SMD; Part Number: TAJA106M016RNJ
C87 C110 C117 = Capacitor_1: Mfr_Name: MURATA; Mfr_Part_Number: GRM155R61C104KA88D; Part Description: CAP CER 0.1UF 16V 10% X5R 0402; Part Number: GRM155R61C104KA88D
C67 C179 C198 = CAP_0201_0.1uF: Mfr_Name: N/A; Note: DNI
C66 C68-C71 C80 C81 C152 C186 C187 C195-C197 C200-C203 C205 C206 = CAP_0201_0.1uF: Mfr_Name: MURATA; Mfr_Part_Number: GRM033R60J104KE19D
J2 = SMA_CONN_0: Distributed by: Digikey; Distributor Part #: J658-ND; MFR's P/N: 142-0701-851; Manufactured by: Johnson; Mfr_Name: JOHNSON; Mfr_Part_Number: 142-0701-851; Part Description: CONN JACK END LAUNCH PC GOLD SMA; Part Number: 142-0701-851; SILK: VIN+
J3 = SMA_CONN_0: Distributed by: Digikey; Distributor Part #: J658-ND; Mfr_Name: JOHNSON; Mfr_Part_Number: 142-0701-851; Part Description: CONN JACK END LAUNCH PC GOLD SMA; Part Number: 142-0701-851; SILK: VIN-
J4 = SMA_CONN_0: Distributed by: Digikey; Distributor Part #: J658-ND; Mfr_Name: JOHNSON; Mfr_Part_Number: 142-0701-851; Part Description: CONN JACK END LAUNCH PC GOLD SMA; Part Number: 142-0701-851; SILK: CLK
J5 = SMA_CONN_0: Distributed by: Digikey; Distributor Part #: J658-ND; Mfr_Name: JOHNSON; Mfr_Part_Number: 142-0701-851; Part Description: CONN JACK END LAUNCH PC GOLD SMA; Part Number: 142-0701-851; SILK: SYSREF
R1 R2 R14 R15 R21 R40 R41 R44 R45 R52 R53 R112 R115 R160-R165 R227 = Resistor_0: Distributed by: Digikey; Distributor Part #: 311-0.0JRCT-ND; Mfr_Name: YAGEO; Mfr_Part_Number: RC0402JR-070RL; Part Description: RES 0.0 OHM 1/16W 0402 SMD; Part Number: RC0402JR-070RL
R3 R10 R24 R25 = Res_0201_Zero_H
R4-R6 R8 R11-R13 R18 R31-R33 R43 R50 R51 R61 R82 R85 R89 R90 R92-R95 R97 R119 = Resistor_0: Mfr_Name: N/A; Note: DNI
R7 R9 = Resistor_0: Distributed by: Digikey; Distributor Part #: P33.0LCT-ND; Mfr_Name: PANASONIC; Mfr_Part_Number: ERJ-2RKF33R0X; Part Description: RES 33.0 OHM 1/10W 1% 0402 SMD; Part Number: ERJ-2RKF33R0X
R16 = Resistor_0: Distributed by: Digikey; Distributor Part #: P10.0LCT-ND; Mfr_Name: PANASONIC; Mfr_Part_Number: ERJ-2RKF10R0X; Part Description: RES 10.0 OHM 1/10W 1% 0402 SMD; Part Number: ERJ-2RKF10R0X
R17 = Res_0402_75
R19 R20 = Res_0402_300
R22 = Resistor_0: Distributed by: Digikey; Distributor Part #: 311-0.0JRCT-ND; Mfr_Name: YAGEO; Mfr_Part_Number: RC0402JR-07100RL_DNI; Note: DNI; Part Description: RES 100 OHM 1/16W 0402 SMD
R23 = Resistor_0: Distributed by: Digikey; Distributor Part #: 311-0.0JRCT-ND; Mfr_Name: YAGEO; Mfr_Part_Number: RC0402FR-07100RL_DNI; Note: DNI; Part Description: RES 100 OHM 1/16W 0402 SMD
R29 = Resistor_0: Distributed by: Digikey; Distributor Part #: P100ABCT-ND; Mfr_Name: PANASONIC; Mfr_Part_Number: ERJ-1GEF1000C; Part Description: RES 100 OHM 1/20W 1% 0201 SMD; Part Number: ERJ-1GEF1000C
R68 R120 = Resistor_0: Mfr_Name: PANASONIC; Mfr_Part_Number: ERJ-2RKF1002X
SW3 = SW_PUSHBUTTON: SILK: SYSREF_SW
T1-T4 = MABA-007159-000000: Distributed by: Mouser; Distributor Part #: 937-MABA007159000000; Mfr_Name: M/A-COM Tech; Part Description: Transformers Audio & Signal 4.5-3000MHz IL 2dB Impedance Ratio 1:1
TP14 = TESTPOINT_WHT: TI_SILKTEXT: BP2.5
TP15 = TESTPOINT_WHT: TI_SILKTEXT: VCM
U1 = ADC14X250_SOCKET_0: Mfr_Name: Texas Instruments; Mfr_Part_Number: ADC14X250RHB
C48 C92 = Cap_0: Mfr_Name: TDK CORP; Mfr_Part_Number: C2012X5R1E106M085AC; Part Description: CAP CER 10UF 25V 20% X5R 0805
C51 = Cap_0: Mfr_Name: MURATA; Mfr_Part_Number: GRM155R61C104KA88D_DNI; Note: DNI; Part Description: CAP CER .1UF 16V X5R 0402; Part Number: GRM155R61C104KA88D
C64 = Capacitor_0: Mfr_Name: TDK CORP; Mfr_Part_Number: C1608C0G1H101J080AA; Part Description: CAP CER 100PF 50V 5% NP0 0603
J6 = SMA_CONN_0: Mfr_Name: JOHNSON; Mfr_Part_Number: 142-0701-851; Part Description: CONN JACK END LAUNCH PC GOLD SMA; SILK: REFCLK
J7 = SMA_CONN_0: Mfr_Name: JOHNSON; Mfr_Part_Number: 142-0701-851; Part Description: CONN JACK END LAUNCH PC GOLD SMA; SILK: EXTREF
L3-L5 L9-L14 = INDUCTOR_FERRITE_SM: Murata Ferrite Bead SM 1.5A; Mfr_Name: MURATA; Mfr_Part_Number: BLM18SG331TN1D; Part Description: FILTER CHIP 330 OHM 1.5A 0603; Part Number: BLM18SG331TN1D
L8 = Inductor_0: Distributed by: Digikey; Distributor Part #: DN42113JCT-ND; Mfr_Name: API DELEVAN INC; Mfr_Part_Number: 1812R-104J; Part Description: INDUCTOR UNSHIELDED 100UH SMD; Part Number: 1812R-104J
LF1_C1 = Capacitor_0: Mfr_Name: TDK CORP; Mfr_Part_Number: C1608C0G1E822J080AA; Part Description: CAP CER 8200PF 25V 5% NP0 0603
LF1_C2 = Capacitor_0: Distributed by: Digikey; Distributor Part #: 399-4919-1-ND; Mfr_Name: KEMET; Mfr_Part_Number: C0603C394K4RACTU; Part Description: CAP CER 0.39UF 16V 10% X7R 0603; Part Number: C0603C394K4RACTU
LF1_R2 = Resistor_0: Distributed by: Digikey; Distributor Part #: 311-3.30KHRCT-ND; Mfr_Name: YAGEO; Mfr_Part_Number: RC0603FR-073K3L; Part Description: RES 3.30K OHM 1/10W 1% 0603 SMD; Part Number: RC0603FR-073K3L
LF2_C1 = Capacitor_0: Distributed by: Digikey; Distributor Part #: 478-1168-1-ND; Mfr_Name: AVX CORP; Mfr_Part_Number: 06035A270JAT2A; Part Description: CAP CER 27PF 50V 5% NP0 0603; Part Number: 06035A270JAT2A
LF2_C2 = Capacitor_0: Mfr_Name: TDK CORP; Mfr_Part_Number: C1608C0G1H272J080AA; Part Description: CAP CER 2700PF 50V 5% NP0 0603
LF2_R2 = Resistor_0: Distributed by: Digikey; Distributor Part #: 311-560HRCT-ND; Mfr_Name: YAGEO; Mfr_Part_Number: RC0603FR-07560RL; Part Description: RES 560 OHM 1/10W 1% 0603 SMD; Part Number: RC0603FR-07560RL
R30 = Res_0402_Zero_DNI: Mfr_Part_Number: ERJ-1GE0R00C_DNI
R34 R36 = Resistor_0: Distributed by: Digikey; Distributor Part #: 541-200LCT-ND; Mfr_Name: Vishay Dale; Mfr_Part_Number: CRCW0402200RFKED; Part Description: RES 200 OHM 1/16W 1% 0402 SMD; Part Number: CRCW0402200RFKED
R35 = Resistor_0: Distributed by: Digikey; Distributor Part #: P49.9LCT-ND; Mfr_Name: PANASONIC; Mfr_Part_Number: ERJ-2RKF49R9X; Part Description: RES 49.9 OHM 1/10W 1% 0402 SMD; Part Number: ERJ-2RKF49R9X
R37 = Resistor_0: Distributed by: Digikey; Distributor Part #: P0.0GCT-ND; Mfr_Name: PANASONIC; Mfr_Part_Number: ERJ-3GEY0R00V; Part Description: RES 0.0 OHM 1/10W 0603 SMD; Part Number: ERJ-3GEY0R00V
R38 R39 = Resistor_0: Distributed by: Digikey; Distributor Part #: 541-200LCT-ND; Mfr_Name: VISHAY DALE; Mfr_Part_Number: CRCW0402200RFKED; Part Description: RES 200 OHM 1/16W 1% 0402 SMD; Part Number: CRCW0402200RFKED
R46-R49 = Resistor_0: Distributed by: Digikey; Distributor Part #: 541-121LCT-ND; Mfr_Name: VISHAY DALE; Mfr_Part_Number: CRCW0402121RFKED; Part Description: RES 121 OHM 1/16W 1% 0402 SMD; Part Number: CRCW0402121RFKED
R54 R55 = Resistor_0: Distributed by: Digikey; Distributor Part #: 541-121LCT-ND; Mfr_Name: Vishay Dale; Mfr_Part_Number: CRCW0402121RFKED; Part Description: RES 121 OHM 1/16W 1% 0402 SMD; Part Number: CRCW0402121RFKED
R110 R111 = Resistor_0: Distributed by: Digikey; Distributor Part #: P1.00KLCT-ND; Mfr_Name: PANASONIC; Mfr_Part_Number: ERJ-2RKF1001X; Part Description: RES 1.00K OHM 1/10W 1% 0402 SMD; Part Number: ERJ-2RKF1001X
R113 R114 = Resistor_0: Mfr_Name: YAGEO; Mfr_Part_Number: RC0402JR-070RL_DNI; Note: DNI; Part Description: RES 0.0 OHM 1/16W 0402 SMD
SW1 = SW_PUSHBUTTON: SILK: LMK_SYNC
SW2 = SW_PUSHBUTTON: SILK: LMK_RESET
T5 = ADT2-1T-1P+_0: Distributed by: Mini-Circuits; Mfr_Name: Mini-Circuits; Part Description: Surface Mount RF Transformer 50 Ohm 8 to 600 MHz
TP16 = TESTPOINT_GRN: Mfr_Part_Number: 5116_DNI; Note: DNI; TI_SILKTEXT: CLKin_SEL1
TP17 = TESTPOINT_GRN: Mfr_Part_Number: 5116_DNI; Note: DNI; TI_SILKTEXT: CLKin_SEL0
TP18 = TESTPOINT_GRN: Mfr_Part_Number: 5116_DNI; Note: DNI; TI_SILKTEXT: Status _LD2
TP19 = TESTPOINT_GRN: Mfr_Part_Number: 5116_DNI; Note: DNI; TI_SILKTEXT: Status_LD1
U13 = LMK04828BISQ: Mfr_Name: Texas Instruments; Mfr_Part_Number: LMK04828BISQ/NOPB; Part Description: Low-Noise Clock Jitter Cleaner with Dual Loop PLLs
Y1 = CCHD-950-61.44: Distributed by: Mouser; Distributor Part #: 549-CCHD-950-25-61.4; Mfr_Name: Crystek Corp; Mfr_Part_Number: CCHD-950-25-61.440_DNI; Note: DNI; Part Description: Standard Clock Oscillators 9X14 25PPM 3.3V HCMOS; Part Number: CCHD-950-25-61.440
Y2 = CWX823-012.288M: Distributed by: Digikey; Distributor Part #: CW439TR-ND; Mfr_Name: Connor-Winfield; Mfr_Part_Number: CWX823-012.288M_DNI; Note: DNI; Part Description: OSC 12.2880MHZ 3.3V +-50PPM SMD
Y3 = CVHD-950-122.88: Distributed by: Digikey; Distributor Part #: 744-1271-ND; Mfr_Name: Crystek Corp; Mfr_Part_Number: CVHD-950-122.880_DNI; Note: DNI; Part Description: VCXO CMOS 122.880 MHZ 3.3V SMD; Part Number: CVHD-950-122.880
J8 = CON_SMVT_40X10_SEAM
Q1 = BSS138_SOT: Mfr_Name: TOSHIBA; Part Description: MOSFET N-CH 20V 250MA VESM
R28 = Res_0402_56
R42 R116 R157 R158 = Resistor_0: Mfr_Name: PANASONIC; Mfr_Part_Number: ERJ-3GEY0R00V; Part Description: RES 0.0 OHM 1/10W 0603 SMD; Part Number: ERJ-3GEY0R00V
R27 R60 R83 R84 R102 = Resistor_0: Mfr_Name: VISHAY DALE; Mfr_Part_Number: CRCW040210K0FKED
R155 R156 = Res_0603_10k_H
SYNC = LED: Green LED; Mfr_Name: Liteon; Mfr_Part_Number: LTST-C170KGKT; Package: SMD; Part Description: LED GREEN CLEAR 0805 SMD; Part Number: LTST-C170KGKT; Terasic_Prt: M0200
C82 C83 = Capacitor_0: Mfr_Name: MURATA; Mfr_Part_Number: GRM155R61C104KA88D; Part Description: CAP CER .1UF 16V X5R 0402; Part Number: GRM155R61C104KA88D
C86 C158 = Cap_0: Mfr_Name: KEMET; Mfr_Part_Number: C0402C470G5GACTU; Part Description: CAP CER 47PF 50V 5% NP0 0402
C96 C102 C109 C122 C132 C145 = Capacitor_0: Mfr_Name: MURATA; Mfr_Part_Number: GRM31CR61E106KA12L; Part Description: CAP CER 10UF 25V X5R 1206; Part Number: GRM31CR61E106KA12L
J9 = USB_MINI_AB_MNE20-5G5P10: Mfr_Name: WURTH ELEKTRONIK; Mfr_Part_Number: 651305142821; Part Description: CONN USB MINI AB 5POS R/A SMD; Part Number: DX3R005HN2E700; TI_SILKTEXT: 5V_USB
R57-R59 R70-R77 = Resistor_0: Mfr_Name: YAGEO; Mfr_Part_Number: RC0402JR-0722RL; Part Description: RES 22 OHM 1/16W 5% 0402 SMD; Part Number: RC0402JR-0722RL
R86 = Resistor_0: Mfr_Name: YAGEO; Mfr_Part_Number: RC0402JR-070RL_DNI; Note: DNI; Part Description: RES 0.0 OHM 1/16W 0402 SMD; Part Number: RC0402JR-070RL
R87 = Resistor_0: Mfr_Name: YAGEO; Mfr_Part_Number: RC0402JR-070RL; Part Description: RES 0.0 OHM 1/16W 0402 SMD; Part Number: RC0402JR-070RL
TP20 = TESTPOINT_RED: TI_SILKTEXT: VSPI1.8
U5 = SN74AVC4T774: Mfr_Name: Texas Instruments; Mfr_Part_Number: SN74AVC4T774PWR; Part Description: IC BUS TRANSCVR 4BIT DL 16TSSOP; Part Number: SN74AVC4T774PWR
U6 = FT245RL: Mfr_Name: FTDI; Mfr_Part_Number: FT245RL-REEL; Part Description: IC USB TO PARALLEL FIFO 28-SSOP; Part Number: FT245RL-REEL
U7 = LP5900SD-??_1: Mfr_Name: Texas Instruments; Part Description: IC REG LDO 1.8V .15A 6-LLP
Z1-Z10 = NFM41_0: Mfr_Name: MURATA; Mfr_Part_Number: NFM41PC204F1H3L; Part Description: FILTER LC HIGH FREQ .2UF 1806; Part Number: NFM41PC204F1H3L
C105 C116 C127 C139 = Capacitor_0: Mfr_Name: KEMET; Mfr_Part_Number: C1206C105K4RACTU; Part Description: CAP 1.0UF 16V CERAMIC X7R 1206; Part Number: C1206C105K4RACTU
C107 C120 C129 C142 = Capacitor_1: Mfr_Name: TDK CORP; Mfr_Part_Number: CGA3E2XR1H222K080AD; Part Description: CAP CER 2200PF 50V X7R 10% 0603
C126 = Cap_Polar_0: Mfr_Name: AVX CORP; Mfr_Part_Number: TCJK476M006R0150; Part Description: CAP TANTALUM 47UF 6.3V 20% SMD
D1 D2 = DIODE_SCHOTTKY_0: Mfr_Name: COMCHIP; Mfr_Part_Number: CDBA140-G
J1 = CONN_JACK_PWR: Mfr_Name: SWITCHCRAFT; Mfr_Part_Number: RAPC722X; SILK: +5V_IN
MT1-MT4 = MOUNTING_HOLE: Mfr_Name: RAF ELECTRONIC; Mfr_Part_Number: 1646-440-AL
R56 R62 = Res_0603_22.1: Mfr_Part_Number: ERJ-PA3J2R0V
R63 R66 R69 R79 R81 R96 = Resistor_0: Mfr_Name: PANASONIC; Mfr_Part_Number: ERJ-2RKF1001X; Part Description: RES 1.00K OHM 1/10W 1% 0402 SMD; Part Number: ERJ-2RKF1001X
R64 = Resistor_0: Mfr_Name: VISHAY DALE; Mfr_Part_Number: CRCW0402200RFKED; Part Description: RES 200 OHM 1/16W 1% 0402 SMD; Part Number: CRCW0402200RFKED
R65 = Resistor_0: Mfr_Name: PANASONIC; Mfr_Part_Number: ERJ-2RKF2002X; Part Description: RES 20.0K OHM 1/16W 1% 0402 SMD; Part Number: CRCW040210K0FKED
R67 = Resistor_0: Mfr_Name: PANASONIC; Mfr_Part_Number: ERJ-2RKF8060X; Part Description: RES 806 OHM 1/10W 1% 0402 SMD; Part Number: ERJ-2RKF8060X
R78 = Resistor_0: Mfr_Name: PANASONIC; Mfr_Part_Number: ERJ-2RKF2001X; Part Description: RES 2.00K OHM 1/10W 1% 0402 SMD; Part Number: ERJ-2RKF2001X
R80 = Resistor_0: Mfr_Name: PANASONIC; Mfr_Part_Number: ERJ-2RKF2321X; Part Description: RES 2.32K OHM 1/16W 1% 0402 SMD
TP1 = TESTPOINT_BLK
TP2 = TESTPOINT_RED: TI_SILKTEXT: VA1.2
TP3 = TESTPOINT_RED: TI_SILKTEXT: VA1.2_AUX
TP4 = TESTPOINT_RED: TI_SILKTEXT: VA1.8
TP5 = TESTPOINT_RED: TI_SILKTEXT: VA3.0
TP6 = TESTPOINT_RED: TI_SILKTEXT: VLMK3.3
TP7 = TESTPOINT_RED: TI_SILKTEXT: V_XO3.3
TP8 = TESTPOINT_RED: TI_SILKTEXT: V_VCX03.3
TP9 = TESTPOINT_BLK: TI_SILKTEXT: GND1
TP10 = TESTPOINT_BLK: TI_SILKTEXT: GND1.2
TP11 = TESTPOINT_BLK: TI_SILKTEXT: GND1.8
TP12 = TESTPOINT_BLK: TI_SILKTEXT: GND3.0
TP13 = TESTPOINT_BLK: TI_SILKTEXT: GND2
TP21 = TESTLOOP_BLACK: Mfr_Name: KEYSTONE; Mfr_Part_Number: 5010; TI_SILKTEXT: +5V
TP22 = TESTLOOP_BLACK: Mfr_Name: KEYSTONE; Mfr_Part_Number: 5011; TI_SILKTEXT: GND
U8-U11 = LP3878MR-ADJ_1: IC VREG 800MA ADJ 8-LLP; Mfr_Name: Texas Instruments; Mfr_Part_Number: LP3878SD-ADJ/NOPB; Part Description: IC VREG 800MA ADJ 8-LLP
Z_BOARD1 = BARE_BOARD: Mfr_Name: TTM; Mfr_Part_Number: ADC14X250 EVM REV B
Z_SCREW1-Z_SCREW4 = STANDOFF-SCREW_3_4

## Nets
+5V: C103.1 C105.1 C114.1 C116.1 C125.1 C127.1 C137.1 C139.1 J1.1 R81.1 R96.1 TP21.1(TP) U8.4(IN) U9.4(IN) U10.4(IN) U11.4(IN)
GND: C1.2 C2.2 C3.1 C4.1 C5.1 C7.2 C8.2 C9.2 C10.2 C11.2 C12.2 C13.2 C14.2 C15.2 C16.2 C17.2 C18.2 C22.2 C23.2 C24.2 C25.2 C26.2 C27.2 C29.1 C31.2 C32.2 C34.2 C35.2 C43.2 C44.2 C45.2 C47.2 C48.2 C55.1 C56.2 C57.2 C58.2 C59.2 C60.2 C61.2 C63.2 C64.2 C65.2 C66.1 C82.1 C83.1 C87.1 C92.2 C93.2 C99.2 C103.2 C104.2 C105.2 C106.1 C108.2 C109.2 C110.1 C111.2 C112.2 C113.2 C114.2 C115.2 C116.2 C117.1 C118.2 C119.1 C121.2 C122.2 C123.2 C125.2 C126.2 C127.2 C128.2 C131.2 C132.2 C133.2 C134.2 C136.2 C137.2 C139.2 C140.2 C141.2 C144.2 C145.2 C146.2 C152.2 C160.2 C164.2 C179.2 C195.1 C197.1 C199.2 C200.2 C201.2 C202.2 C203.2 C204.2 C205.2 C206.2 J1.2 J1.3 J2.2(SHIELD2) J2.3(SHIELD3) J2.4(SHIELD4) J2.5(SHIELD5) J3.2(SHIELD2) J3.3(SHIELD3) J3.4(SHIELD4) J3.5(SHIELD5) J4.2(SHIELD2) J4.3(SHIELD3) J4.4(SHIELD4) J4.5(SHIELD5) J5.2(SHIELD2) J5.3(SHIELD3) J5.4(SHIELD4) J5.5(SHIELD5) J6.2(SHIELD2) J6.3(SHIELD3) J6.4(SHIELD4) J6.5(SHIELD5) J7.2(SHIELD2) J7.3(SHIELD3) J7.4(SHIELD4) J7.5(SHIELD5) J8.A1 J8.A4 J8.A5 J8.A8 J8.A9 J8.A12 J8.A13 J8.A16 J8.A17 J8.A20 J8.A21 J8.A24 J8.A25 J8.A28 J8.A29 J8.A32 J8.A33 J8.A36 J8.A37 J8.A40 J8.B2 J8.B3 J8.B6 J8.B7 J8.B10 J8.B11 J8.B15 J8.B18 J8.B19 J8.B22 J8.B23 J8.B26 J8.B27 J8.B30 J8.B31 J8.B34 J8.B35 J8.B38 J8.B39 J8.C1 J8.C4 J8.C5 J8.C8 J8.C9 J8.C12 J8.C13 J8.C16 J8.C17 J8.C20 J8.C21 J8.C24 J8.C25 J8.C28 J8.C29 J8.C32 J8.C33 J8.C36 J8.C38 J8.C40 J8.D2 J8.D3 J8.D6 J8.D7 J8.D10 J8.D13 J8.D16 J8.D19 J8.D22 J8.D25 J8.D28 J8.D37 J8.D39 J8.E1 J8.E4 J8.E5 J8.E8 J8.E11 J8.E14 J8.E17 J8.E20 J8.E23 J8.E26 J8.E29 J8.E32 J8.E35 J8.E38 J8.E40 J8.F2 J8.F3 J8.F6 J8.F9 J8.F12 J8.F15 J8.F18 J8.F21 J8.F24 J8.F27 J8.F30 J8.F33 J8.F36 J8.F39 J8.G1 J8.G4 J8.G5 J8.G8 J8.G11 J8.G14 J8.G17 J8.G20 J8.G23 J8.G26 J8.G29 J8.G32 J8.G35 J8.G38 J8.G40 J8.H2 J8.H3 J8.H6 J8.H9 J8.H12 J8.H15 J8.H18 J8.H21 J8.H24 J8.H27 J8.H30 J8.H33 J8.H36 J8.H39 J8.J1 J8.J4 J8.J5 J8.J8 J8.J11 J8.J14 J8.J17 J8.J20 J8.J23 J8.J26 J8.J29 J8.J32 J8.J35 J8.J38 J8.J40 J8.K2 J8.K3 J8.K6 J8.K9 J8.K12 J8.K15 J8.K18 J8.K21 J8.K24 J8.K27 J8.K30 J8.K33 J8.K36 J8.K39 LF1_C1.2 LF1_R2.2 LF2_C1.2 LF2_R2.2 Q1.2(S) R1.2 R2.2 R4.1 R14.2 R19.2 R20.2 R22.2 R23.2 R27.1 R32.1 R35.1 R36.1 R39.1 R46.1 R47.1 R48.1 R49.1 R52.2 R53.2 R54.1 R55.1 R63.2 R66.2 R69.2 R79.2 R82.2 R87.1 R89.1 R90.1 R97.2 R102.1 R110.2 R111.2 R120.2 R155.2 T5.2 T5.3 T5.5 TP1.1(TP) TP9.1(TP) TP10.1(TP) TP11.1(TP) TP12.1(TP) TP22.1(TP) U1.2(AGND) U1.5(AGND) U1.8(AGND) U1.11(AGND) U1.18(AGND) U1.21(AGND) U1.27(AGND) U1.30(AGND) U1.31(AGND) U1.33(DAP) U1.34(MT1) U1.35(MT2) U1.36(MT3) U1.37(MT4) U5.1(DIR1) U5.2(DIR2) U5.8(DIR4) U5.10(GND) U5.14(B1) U8.3(GND) U8.DAP U9.3(GND) U9.DAP U10.3(GND) U10.DAP U11.3(GND) U11.DAP U13.65(DAP) Y1.3(GND) Y2.2(GND) Y3.3(GND) Z2.2 Z2.3 Z4.2 Z5.2 Z6.2 Z7.2 Z8.2 Z9.2 Z10.2
GND2: C84.2 C86.2 C95.2 C96.2 C102.2 C158.2 C161.2 C162.2 J9.5(GND) J9.6(GND1) J9.7(GND2) J9.8(GND3) J9.9(GND4) TP13.1(TP) U6.7(GND) U6.18(GND) U6.21(GND) U6.25(AGND) U6.26(TEST) U7.3(GND) U7.7(DAP) Z1.2 Z2.1 Z3.2
VIN+: R24.2 U1.3(VIN+)
VIN-: R25.2 U1.4(VIN-)
VINN: R4.2 R15.2 T1.4
VINN+: C17.1 C19.1 R3.2 R7.1 R13.2 R24.1
VINN-: C19.2 C23.1 R6.2 R9.1 R10.2 R25.1
VINP: R11.2 R14.1 T1.6
ADC_CSb: R77.2 R83.1 R85.1 R95.2 U1.23(CSB)
ADC_SCLK: R70.2 R92.2 U1.24(SCLK)
ADC_SDI: R73.2 R93.1 U1.25(SDI)
ADC_SDO: R72.2 R94.1 U1.26(SDO)
BP2p5: C43.1 C44.1 C45.1 TP14.1(TP) U1.22(BP2.5)
CLKIN+: R18.2 R40.2 R43.2 U1.9(CLKIN+)
CLKIN-: R18.1 R41.2 R50.2 U1.10(CLKIN-)
CLKOUT2+: C71.1 R49.2 U13.15(DCLKout2)
CLKOUT2-: C70.1 R48.2 U13.16(DCLKout2*)
CLKOUT3+: C69.1 R47.2 U13.13(SDCLKout3)
CLKOUT3-: C68.1 R46.2 U13.14(SDCLKout3*)
CLKOUT4+: C81.1 R55.2 U13.24(DCLKout4)
CLKOUT4-: C80.1 R54.2 U13.25(DCLKout4*)
CLKOUT8+: R165.1 U13.51(DCLKout8)
CLKOUT8-: R164.1 U13.52(DCLKout8*)
CLKOUT10+: R163.1 U13.54(DCLKout10)
CLKOUT10-: R162.1 U13.55(DCLKout10*)
CLKOUT11+: R161.1 U13.56(SDCLKout11)
CLKOUT11-: R160.1 U13.57(SDCLKout11*)
CSb_LMK_3p3: R57.2 U13.18(CS*)
EXT_CLK+: R40.1 T3.4
EXT_CLK-: R41.1 T3.6
EXT_REF: J7.1(CENTER) R34.1 R35.2
EXT_SYSREF+: R44.1 T4.4
EXT_SYSREF-: R45.1 T4.6
EXTREF: R17.2 R20.1 R227.2
EXTREF_XO: C159.1 R33.1 R34.2 R36.2 R227.1
EXTXO: R33.2 Y1.4(RF) Y2.3(OUT)
FMC_FPGA_DEVCLKA+: J8.D4 R165.2
FMC_FPGA_DEVCLKA-: J8.D5 R164.2
FMC_FPGA_DEVCLKB+: J8.G6 R163.2
FMC_FPGA_DEVCLKB-: J8.G7 R162.2
FMC_FPGA_SYSREF+: J8.G9 R161.2
FMC_FPGA_SYSREF-: J8.G10 R160.2
LMK_ADC_DEVCLK+: C70.2 R43.1
LMK_ADC_DEVCLK-: C71.2 R50.1
LMK_ADC_SYSREF+: C68.2 R51.1
LMK_ADC_SYSREF-: C69.2 R61.1
LMK_CSb: R75.2 R84.1 U5.13(B2)
LMK_DIR: R27.2 R74.2 U5.7(DIR3)
LMK_RESET: C110.2 R110.1 R112.2 R113.2 U13.5(RESET)
LMK_RESET_FMC: J8.G24 R113.1
LMK_SCLK: R71.2 U5.11(B4)
LMK_SDIO: R76.2 U5.12(B3)
LMK_SYNC: C117.2 R111.1 R114.2 R115.2 U13.6(SYNC)
LMK_SYNC_FMC: J8.G25 R114.1
LMK_VCC1/5/6: C61.1 C118.1 C160.1 C199.1 L3.1 U13.10(Vcc1_VCO) U13.33(Vcc5_DIG) U13.36(Vcc6_PLL1)
LMK_VCC2: C152.1 L4.2 U13.17(Vcc2_CG1)
LMK_VCC3: C200.1 L9.2 U13.21(Vcc3_SYSREF)
LMK_VCC4: C201.1 L10.2 U13.26(Vcc4_CG2)
LMK_VCC7: C206.1 L13.2 U13.39(Vcc7_OSCout)
LMK_VCC8/10: C141.1 C164.1 C204.1 L5.1 L13.1 L14.1 U13.42(Vcc8_OSCin) U13.47(Vcc10_PLL2)
LMK_VCC9: C205.1 L14.2 U13.45(Vcc9_CP2)
LMK_VCC11: C202.1 L11.2 U13.53(Vcc11_CG3)
LMK_VCC12: C203.1 L12.2 U13.64(Vcc12_CG0)
PG_C2M: J8.D1 R155.1
PG_M2C: J8.F1 R156.2
REFCLK: J6.1(CENTER) T5.1
REFCLK+: C81.2 T5.6
REFCLK-: C80.2 T5.4
SCLK_LMK_3p3: R58.2 U13.19(SCK)
SDIO_LMK_3p3: R59.2 U13.20(SDIO)
SO+: C37.2 J8.C6
SO-: C36.2 J8.C7
SSYSREF+: C186.2 R29.2 R44.2 R51.2
SSYSREF-: C187.2 R29.1 R45.2 R61.2
STATUS_LD1: TP19.1(TP) U13.31(Status_LD1)
STATUS_LD2: TP18.1(TP) U13.48(Status_LD2)
SYNCb+: J8.G12 U1.15(SYNCb+)
SYNCb-: J8.G13 U1.16(SYNCb-)
SYSREF+: C186.1 R119.1 U1.13(SYSREF+)
SYSREF-: C179.1 C187.1 U1.14(SYSREF-)
T1+: C20.1 T1.1
T1-: C21.1 T1.3
V_VCXO3.3: C59.1 C60.1 C140.1 C146.1 L8.1 TP8.1(TP) Z10.3
V_XO3.3: C58.1 C134.1 C136.1 R31.2 TP7.1(TP) Y1.6(Vs) Y2.4(Vcc) Z9.3
VA1.2: C3.2 C5.2 C9.1 C10.1 C11.1 C12.1 C99.1 C104.1 SW3.1 TP2.1(TP) U1.7(VA1.2) U1.28(VA1.2) Z4.3
VA1.2_AUX: C4.2 C34.1 C35.1 C111.1 C112.1 TP3.1(TP) U1.17(VA1.2) Z5.3
VA1.8: C7.1 C8.1 C13.1 C15.1 C18.1 C24.1 C113.1 C115.1 R83.2 R84.2 TP4.1(TP) U1.12(VA1.8) U1.29(VA1.8) U1.32(VA1.8) Z6.3
VA3.0: C1.1 C2.1 C123.1 C126.1 R28.1 R65.2 R68.1 TP5.1(TP) U1.1(VA3.0) Z7.3
VADJ: J8.E39 J8.F40 J8.G39 J8.H40 R42.1 R156.1
VCM: C22.1 C32.1 R7.2 R8.2 R9.2 R16.1 TP15.1(TP)
VCMODE: C25.1 C26.1 C27.1 R16.2 U1.6(VCM)
VIO_B_M2C: J8.J39 J8.K40 R42.2
VLMK3.3: C82.2 C92.1 C93.1 C128.1 C133.1 L3.2 L4.1 L5.2 L9.1 L10.1 L11.1 L12.1 R86.1 SW1.1 SW2.1 TP6.1(TP) U5.16(VCCA) Z8.3
VN: J3.1(CENTER) R5.1 R15.1
VP: J2.1(CENTER) R11.1 R12.1
VSPI1.8: C83.2 C95.1 C162.1 R60.2 R85.2 TP20.1(TP) U5.15(VCCB) U6.4(VCCIO) Z3.3
N17161280: C129.1 C132.1 R56.2 R78.2 U10.5(OUT) Z7.1
N17161284: R96.2 R97.1 U10.8(~{SD})
N17161345: C129.2 R69.1 R78.1 U10.6(ADJ)
N17161357: C131.1 U10.1(BYPASS)
N17161499: C142.1 C145.1 R80.2 U11.5(OUT) Z8.1 Z9.1 Z10.1
N17161629: R81.2 R82.1 U11.8(~{SD})
N17161669: C142.2 R79.1 R80.1 U11.6(ADJ)
N17161679: C144.1 U11.1(BYPASS)
N17161879: C107.1 C109.1 D2.1(ANODE) R64.2 U8.5(OUT) Z4.1 Z5.1
N17161936: C106.2 R65.1 R89.2 U8.8(~{SD})
N17162041: C120.1 C122.1 D1.1(ANODE) R62.2 R67.2 U9.5(OUT) Z6.1
N17162051: C119.2 R68.2 R90.2 U9.8(~{SD})
N17162120: C120.2 R66.1 R67.1 U9.6(ADJ)
N17162132: C121.1 U9.1(BYPASS)
N17162350: C107.2 R63.1 R64.1 U8.6(ADJ)
N17162360: C108.1 U8.1(BYPASS)
N17167241: C158.1 J9.2(D-) U6.16(USBDM)
N17167387: C102.1 U7.1(VOUT) Z3.1
N17167421: C96.1 R157.2 U7.4(EN) U7.6(VIN)
N17167654: R70.1 U6.1(D0)
N17167656: R73.1 U6.5(D1)
N17167658: R72.1 U6.3(D2)
N17167660: R77.1 U6.11(D3)
N17167662: R71.1 U6.2(D4)
N17167664: R75.1 U6.9(D5)
N17167666: R76.1 U6.10(D6)
N17167668: R74.1 U6.6(D7)
N17167775: R58.1 U5.6(A4)
N17167777: R59.1 U5.5(A3)
N17167779: R57.1 U5.4(A2)
N17167819: C86.1 J9.3(D+) U6.15(USBDP)
N17168074: C84.1 U6.17(3V3OUT)
N17168078: R60.1 U6.12(~{PWREN})
N17168092: J9.1(VBUS) Z1.1
N17168106: C161.1 R158.2 U6.20(VCC)
N17215258: C16.1 T1.2 T1.5
N17215302: C20.2 T2.6
N17215394: C14.1 R8.1 T2.2 T2.5
N17215600: R3.1 T2.1
N17215624: C21.2 T2.4
N17215642: R10.1 T2.3
N17220421: C31.1 T3.2 T3.5
N17225099: C56.1 T4.2 T4.5
N17242573: C36.1 U1.20(SO-)
N17242594: C37.1 U1.19(SO+)
N17273940: R157.1 R158.1 Z1.3
N17303725: LF2_C1.1 LF2_C2.1 U13.46(CPout2)
N17303875: C63.1 R37.2 Y3.1(Vtune)
N17303984: C64.1 C65.1 L8.2 Y3.6(Vs)
N17304319: LF2_C2.2 LF2_R2.1
N17304368: R38.2 Y3.4(RF)
N17304374: C51.2 R38.1 R39.2
N17304410: C57.1 R31.1 R32.2 Y1.1(Vtune) Y2.1(EN)
N17304458: C66.2 U13.44(OSCin*)
N17304625: LF1_C1.1 LF1_C2.1 R37.1 U13.32(CPout1)
N17305040: C51.1 C67.1 R30.1
N17305042: C67.2 U13.43(OSCin)
N17305088: C195.2 U13.35(CLKin1*/Fin*/FBCLKin*)
N17305090: C159.2 C196.1 C198.1 R30.2
N17305092: C196.2 U13.34(CLKin1/Fin/FBCLKin)
N17305106: C197.2 U13.38(CLKin0*)
N17305110: C198.2 U13.37(CLKin0)
N17305389: R112.1 SW2.2
N17305438: R115.1 SW1.2
N17320541: TP16.1(TP) U13.59(CLKin_SEL1)
N17320545: TP17.1(TP) U13.58(CLKin_SEL0)
N17320732: C47.1 U13.12(LDObyp2)
N17320734: C48.1 U13.11(LDObyp1)
N17329800: C87.2 R119.2 R120.1 SW3.2
N17424784: J8.D31 R116.2
N17424792: J8.D30 R116.1
N17424855: J8.H31 Q1.1(G) R102.2
N17425083: J8.H37 R92.1
N17425085: J8.H38 R95.1
N17425095: Q1.3(D) SYNC.2(CATHODE)
N17425908: J8.G36 R93.2
N17425910: J8.G37 R94.2
N17439983: LF1_C2.2 LF1_R2.1
N17456786: C28.1 J4.1(CENTER) R21.2 R22.1
N17456846: C53.1 J5.1(CENTER) R23.1
N17469287: R1.1 R12.2 R13.1 R52.1
N17469485: R2.1 R5.2 R6.1 R53.1
N17474156: C53.2 T4.3
N17474169: C55.2 T4.1
N17474172: C29.2 T3.1
N17474175: C28.2 T3.3
N17476146: R17.1 R19.1 R21.1
N17481569: R86.2 R87.2 U5.9(OEb)
N17576943: D2.2(CATHODE) R62.1
N17577005: D1.2(CATHODE) R56.1
N17610512: R28.2 SYNC.1(ANODE)

Not connected (* = marked no-connect by the designer): J8 A2 A3 A6 A7 A10 A11 A14 A15 A18 A19 A22 A23 A26 A27 A30 A31 A34 A35 A38 A39 B1 B4 B5 B8 B9 B12 B13 B14 B16 B17 B20 B21 B24 B25 B28 B29 B32 B33 B36 B37 B40 C2 C3 C10 C11 C14 C15 C18 C19 C22 C23 C26 C27 C30 C31 C34 C35 C37 C39 D8 D9 D11 D12 D14 D15 D17 D18 D20 D21 D23 D24 D26 D27 D29 D32 D33 D34 D35 D36 D38 D40 E2 E3 E6 E7 E9 E10 E12 E13 E15 E16 E18 E19 E21 E22 E24 E25 E27 E28 E30 E31 E33 E34 E36 E37 F4 F5 F7 F8 F10 F11 F13 F14 F16 F17 F19 F20 F22 F23 F25 F26 F28 F29 F31 F32 F34 F35 F37 F38 G2 G3 G15 G16 G18 G19 G21 G22 G27 G28 G30 G31 G33 G34 H1 H4 H5 H7 H8 H10 H11 H13 H14 H16 H17 H19 H20 H22 H23 H25 H26 H28 H29 H32 H34 H35 J2 J3 J6 J7 J9 J10 J12 J13 J15 J16 J18 J19 J21 J22 J24 J25 J27 J28 J30 J31 J33 J34 J36 J37 K1 K4 K5 K7 K8 K10 K11 K13 K14 K16 K17 K19 K20 K22 K23 K25 K26 K28 K29 K31 K32 K34 K35 K37 K38; J9 4(ID)*; MT1 1*; MT2 1*; MT3 1*; MT4 1*; U5 3(A1)*; U6 8(NC)* 13(~{RD})* 14(WR)* 19(~{RESET})* 22(~{TXE})* 23(~{RXF})* 24(NC)* 27(OSCI)* 28(OSCO)*; U7 2(N/C2)* 5(N/C5)*; U8 2(N/C1)* 7(N/C2)*; U9 2(N/C1)* 7(N/C2)*; U10 2(N/C1)* 7(N/C2)*; U11 2(N/C1)* 7(N/C2)*; U13 1(DCLKout0)* 2(DCLKout0*)* 3(SDCLKout1)* 4(SDCLKout1*)* 7(NC)* 8(NC)* 9(NC)* 22(SDCLKout5)* 23(SDCLKout5*)* 27(DCLKout6)* 28(DCLKout6*)* 29(SDCLKout7)* 30(SDCLKout7*)* 40(OSCout)* 41(OSCout*)* 49(SDCLKout9)* 50(SDCLKout9*)* 60(SDCLKout13)* 61(SDCLKout13*)* 62(DCLKout12)* 63(DCLKout12*)*; Y1 2(NC)* 5(RF*)*; Y3 2(NC)* 5(RF*)*

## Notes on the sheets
sheet 1
- ADC
- CLOCK INPUT
- ADCCLK
- USB I/F
- ADC14X250
- LMK04828
- PAGE 5
- SYSREF
- PAGE 2
- PAGE 3
- JESD204B
- INTERFACE
- PAGE 4
- POWER SUPPLIES
- PAGE 6
- Drawn:
- L NGUYEN 9/2015
- Engineer:
- J CARNES   9/2015
sheet 2
- R1 & R12 share a pad.
- R13 & R52 share a pad.
- R3 & R13 share a pad.
- R11 & R12 share a pad.
- R2 & R5 share a pad.
- R6 & R53 share a pad.
- R5 & R15 share a pad.
- R6 & R10 share a pad.
- CLKIN & SYSREF MUST MATCH IN TOTAL LENGTH.
sheet 4
- DP0_M2C_P
- LA00_P_CC
- DP0_M2C_N
- LA00_P_CC
- LA03_P
- LA03_N
- LA08_P
- LA08_N
- LA22_P
- LA22_N
- ADC_SDI
- ADC_SDO
- PRSNT_M2C_L
- GBTCLKO_M2C_P
- GBTCLKO_M2C_N
- D30/31 short required
  for KC705 board
- ADC_SCLK
- ADC_CSb
